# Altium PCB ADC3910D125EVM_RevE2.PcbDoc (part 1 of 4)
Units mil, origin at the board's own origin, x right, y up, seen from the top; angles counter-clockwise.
Board outline 4000 x 2716.54 mil, 6 copper layers (Top Layer, L2 GND, L3 PWR, L4 PWR, L5 GND, Bottom Layer), stack 60.99 mil thick; 318 components, 203 nets, 1298 pads, 559 vias.
Unrouted connection lines stored in the file: 5.
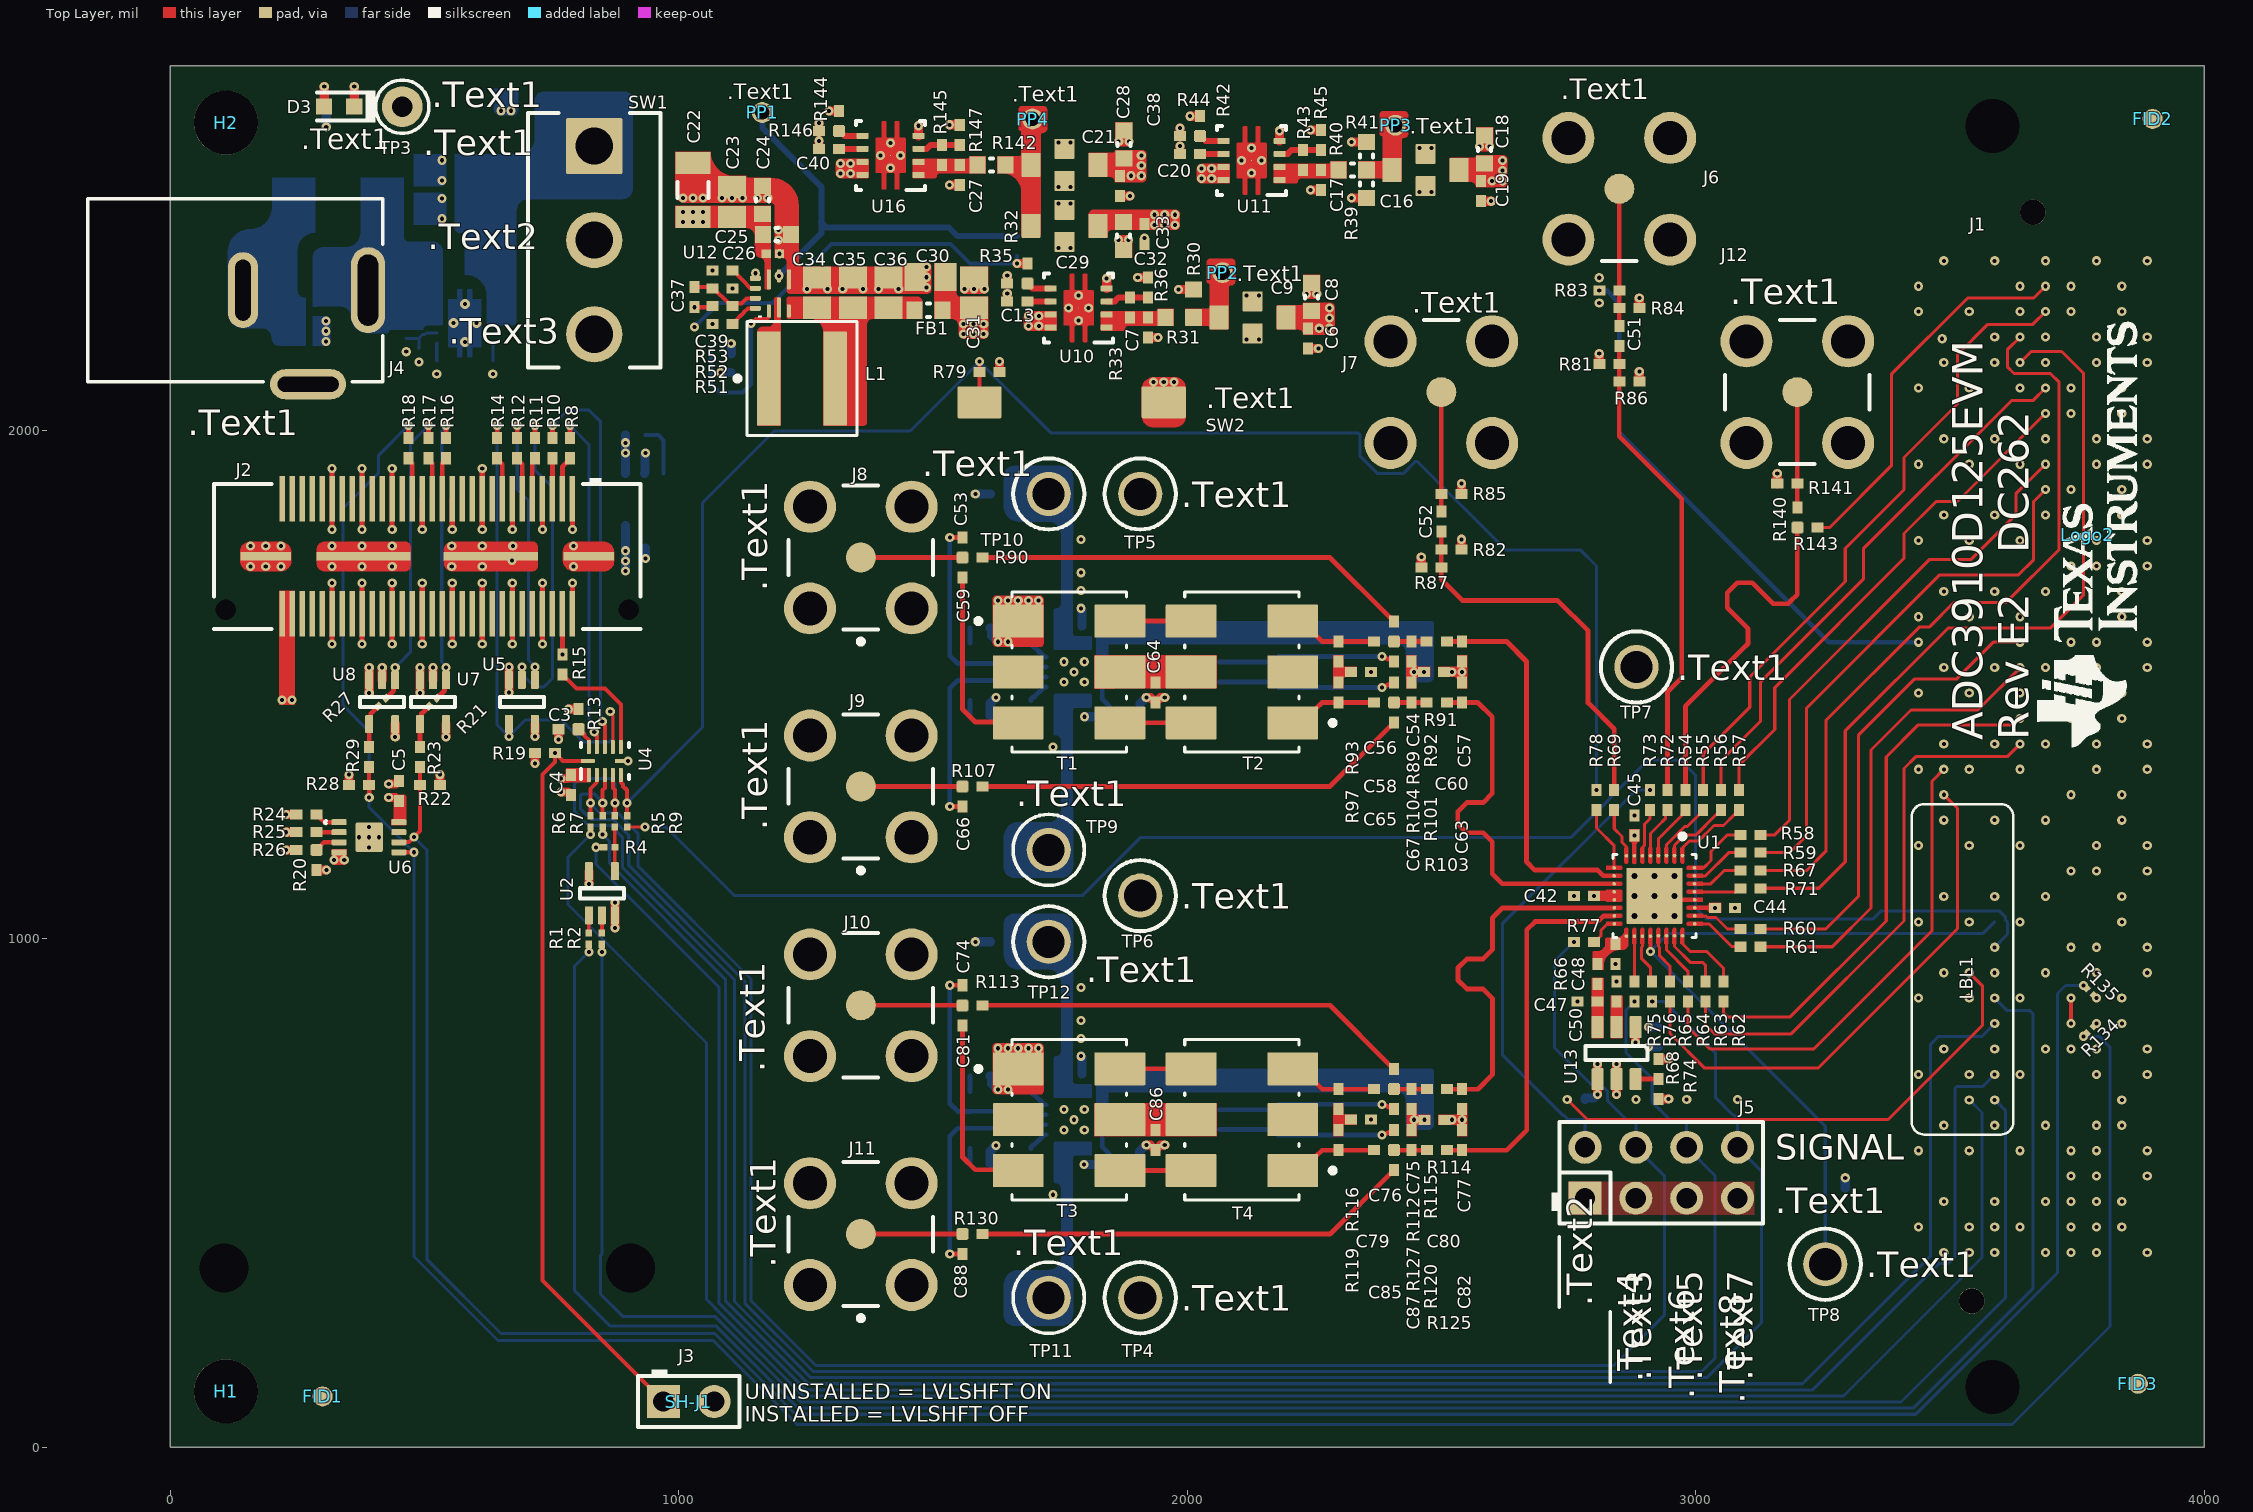
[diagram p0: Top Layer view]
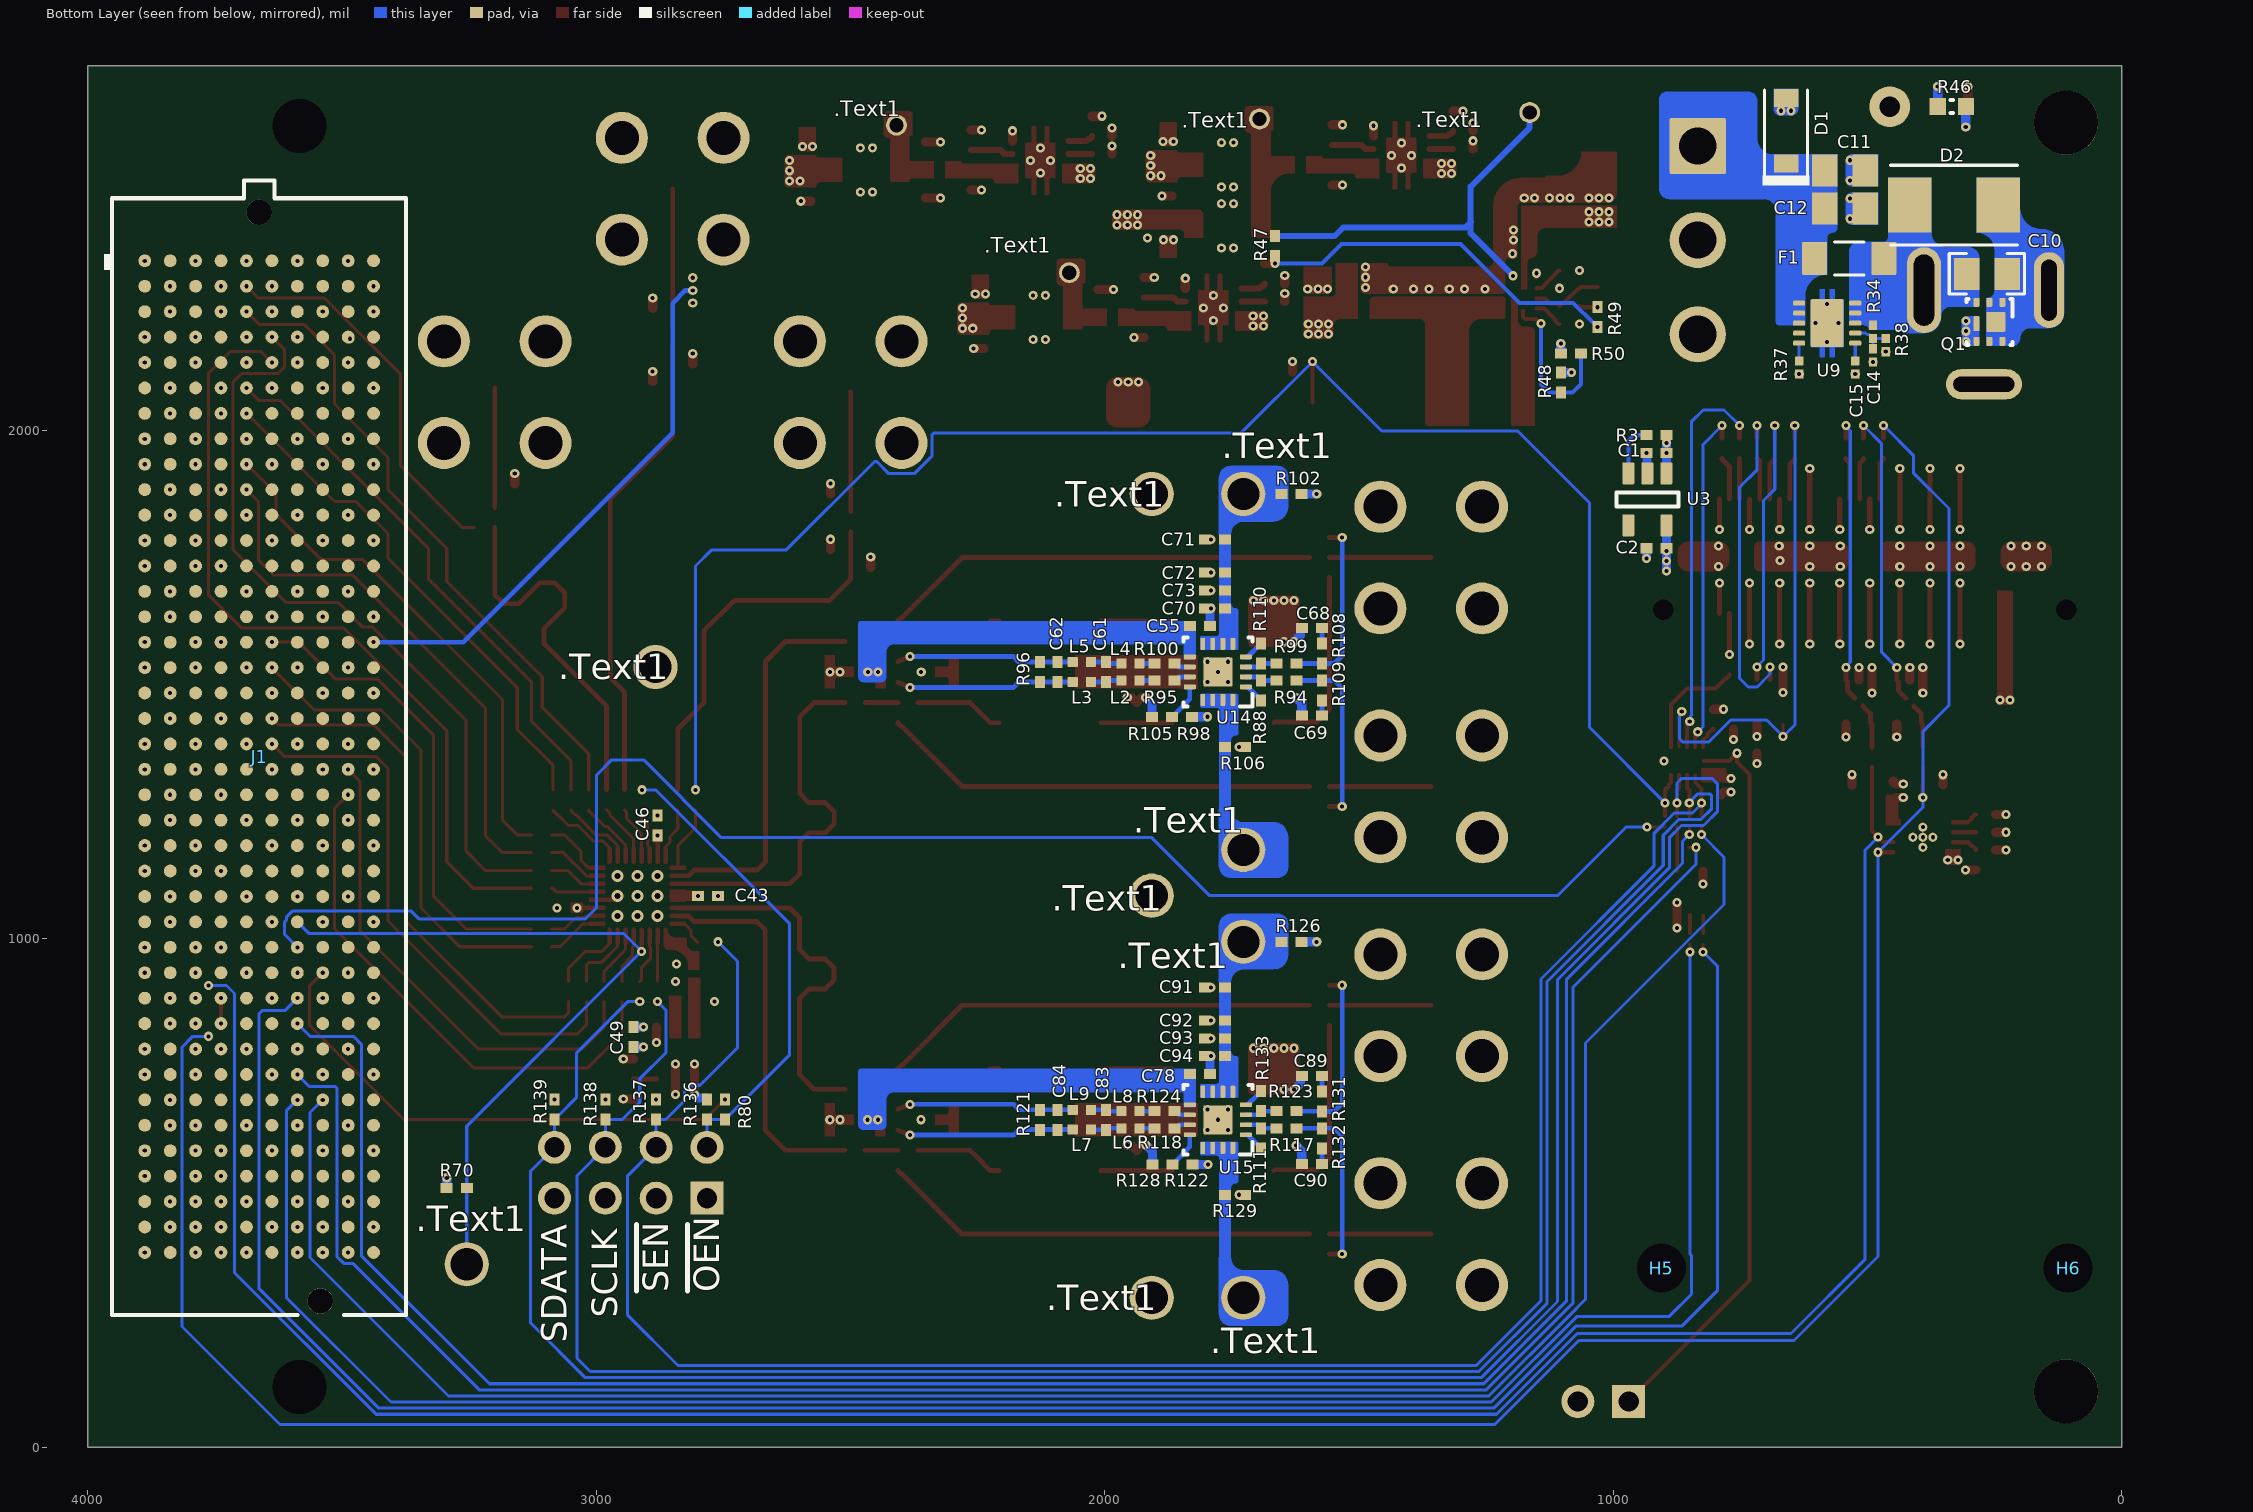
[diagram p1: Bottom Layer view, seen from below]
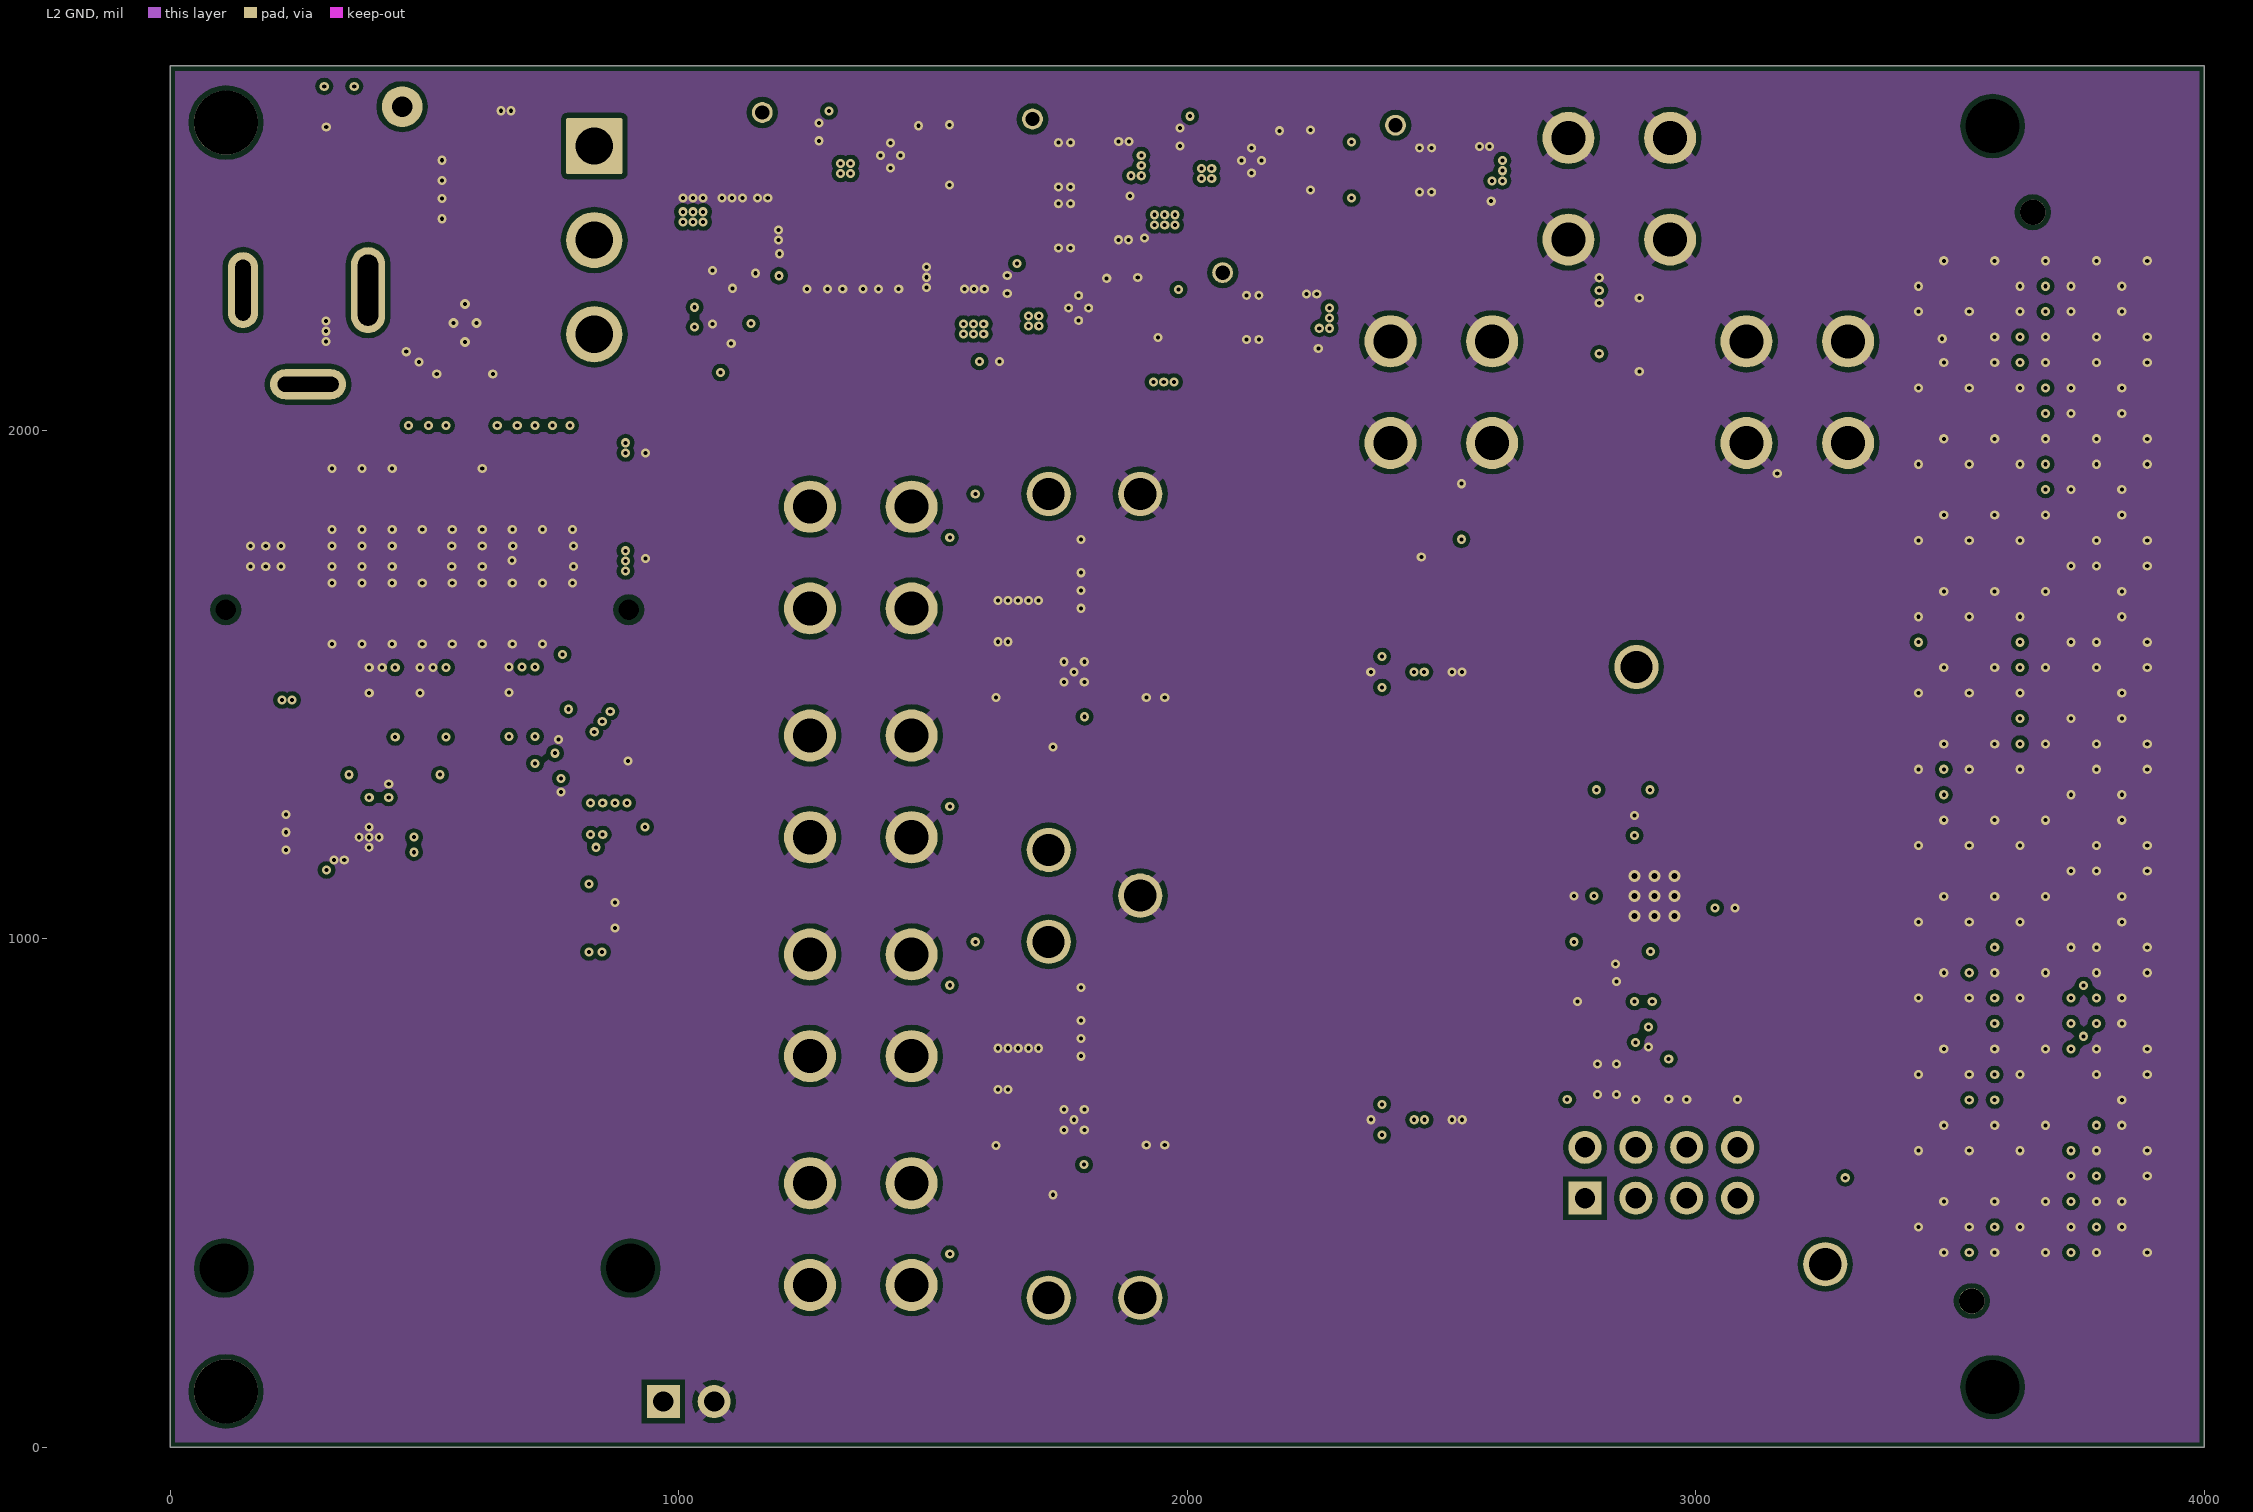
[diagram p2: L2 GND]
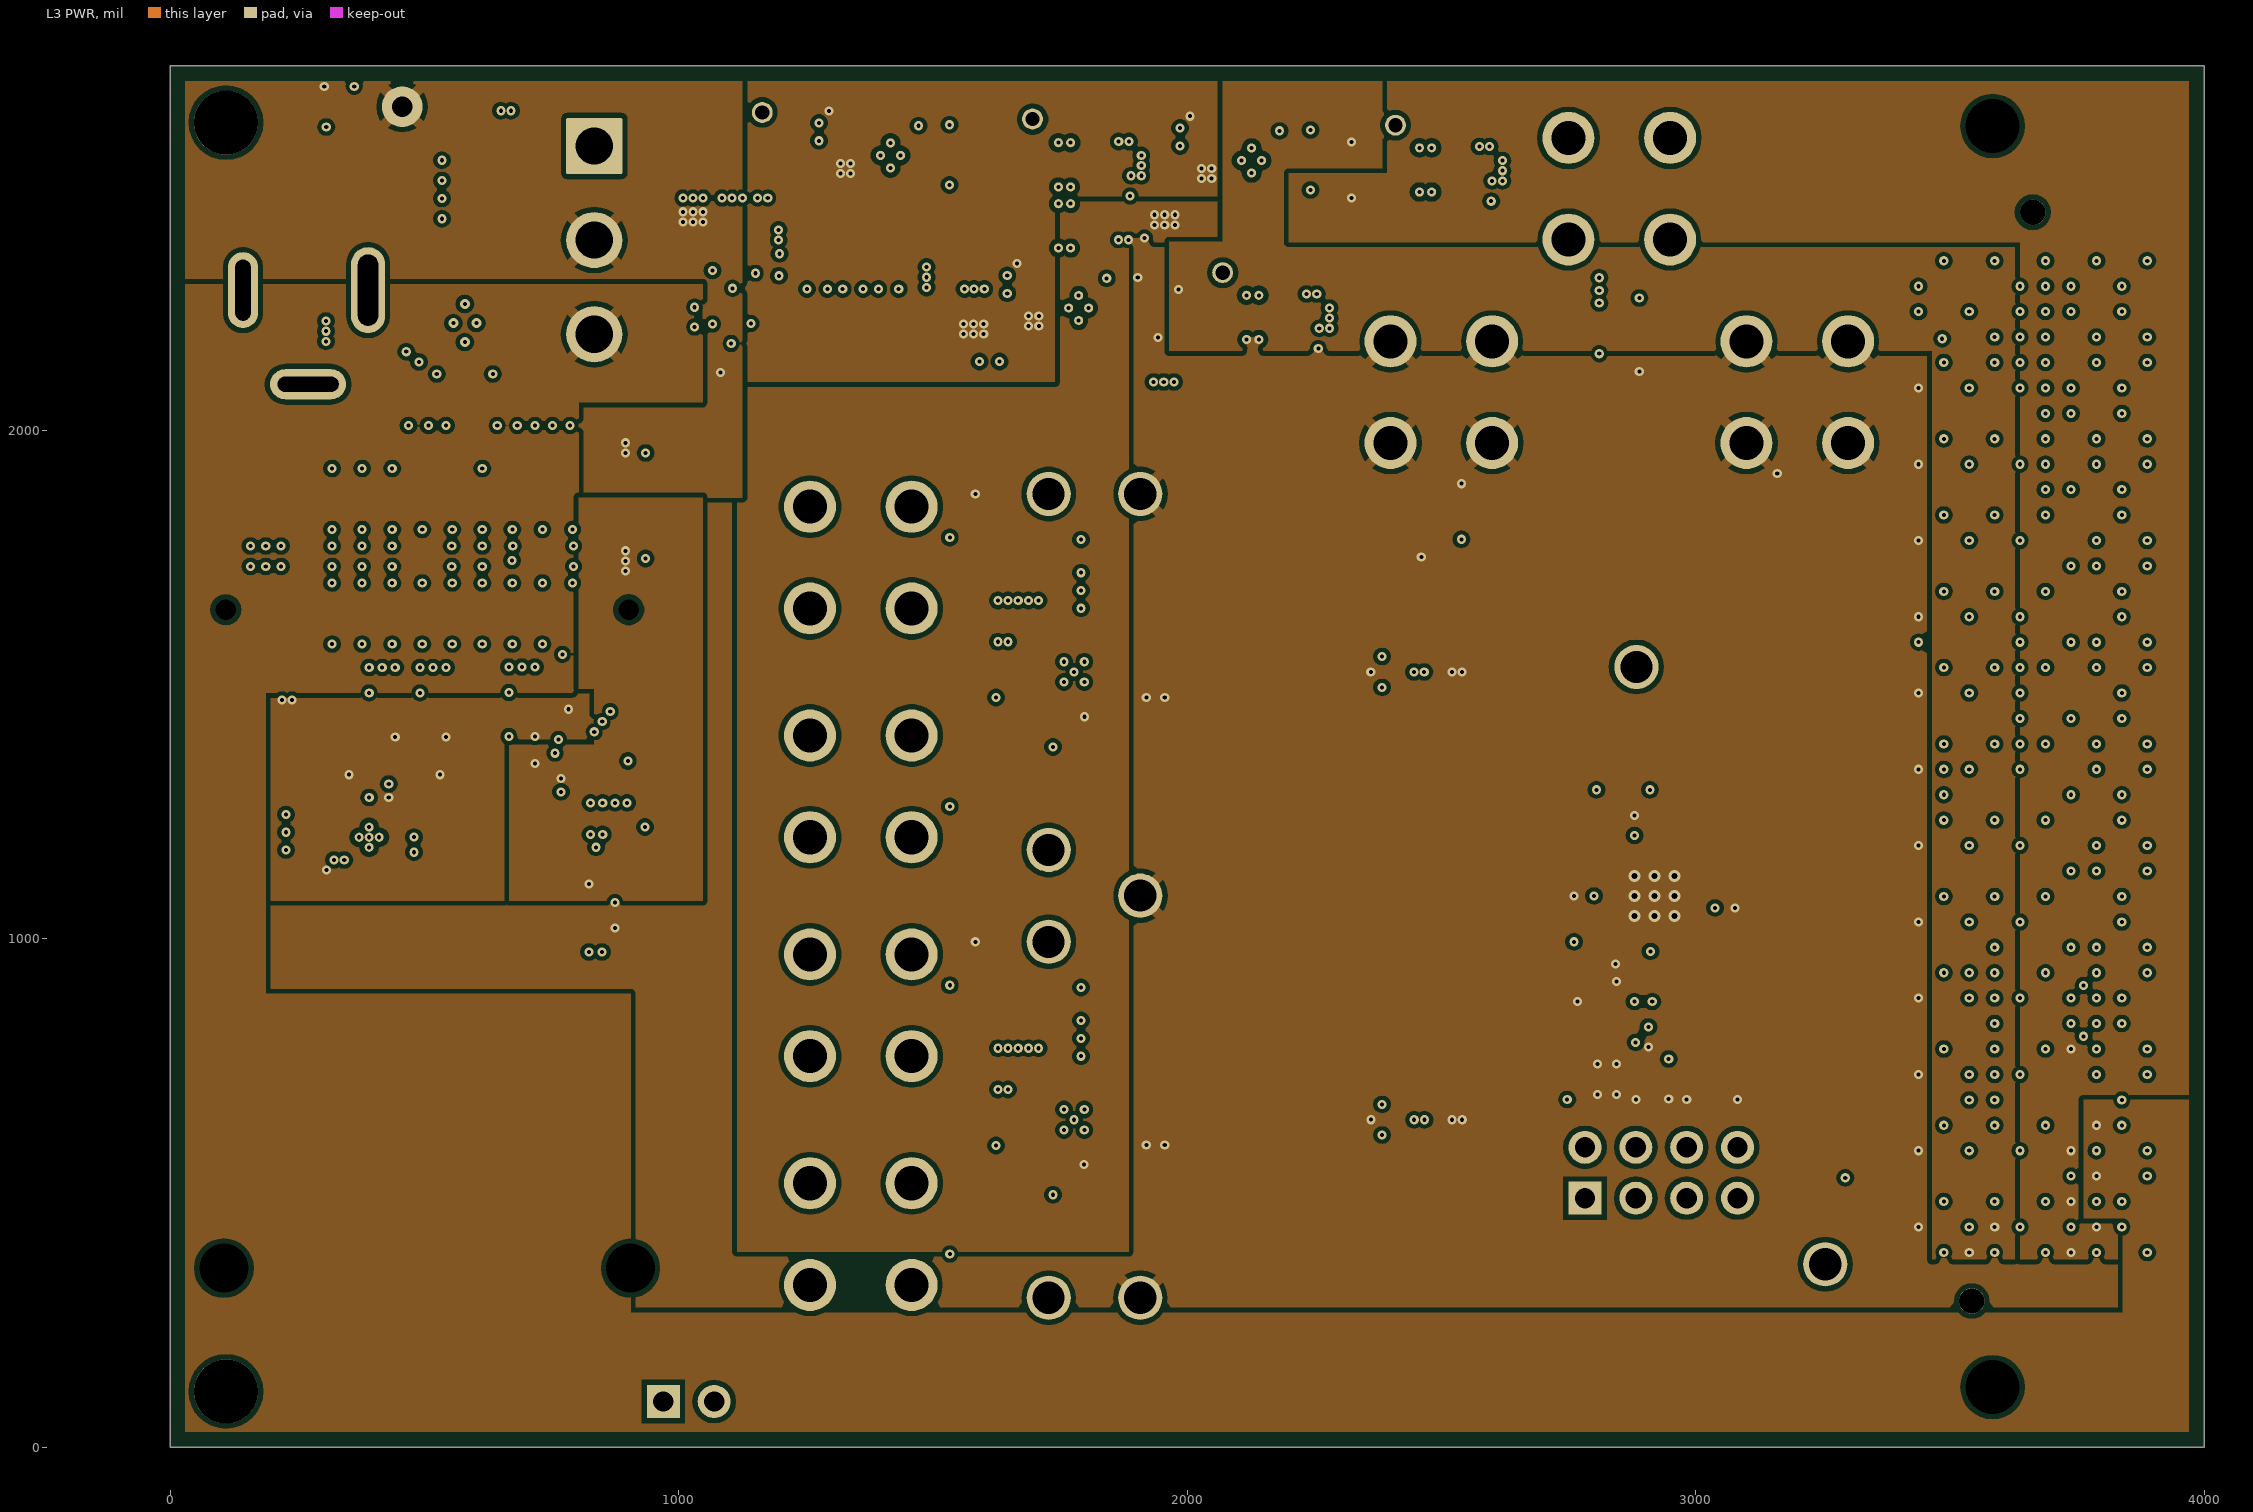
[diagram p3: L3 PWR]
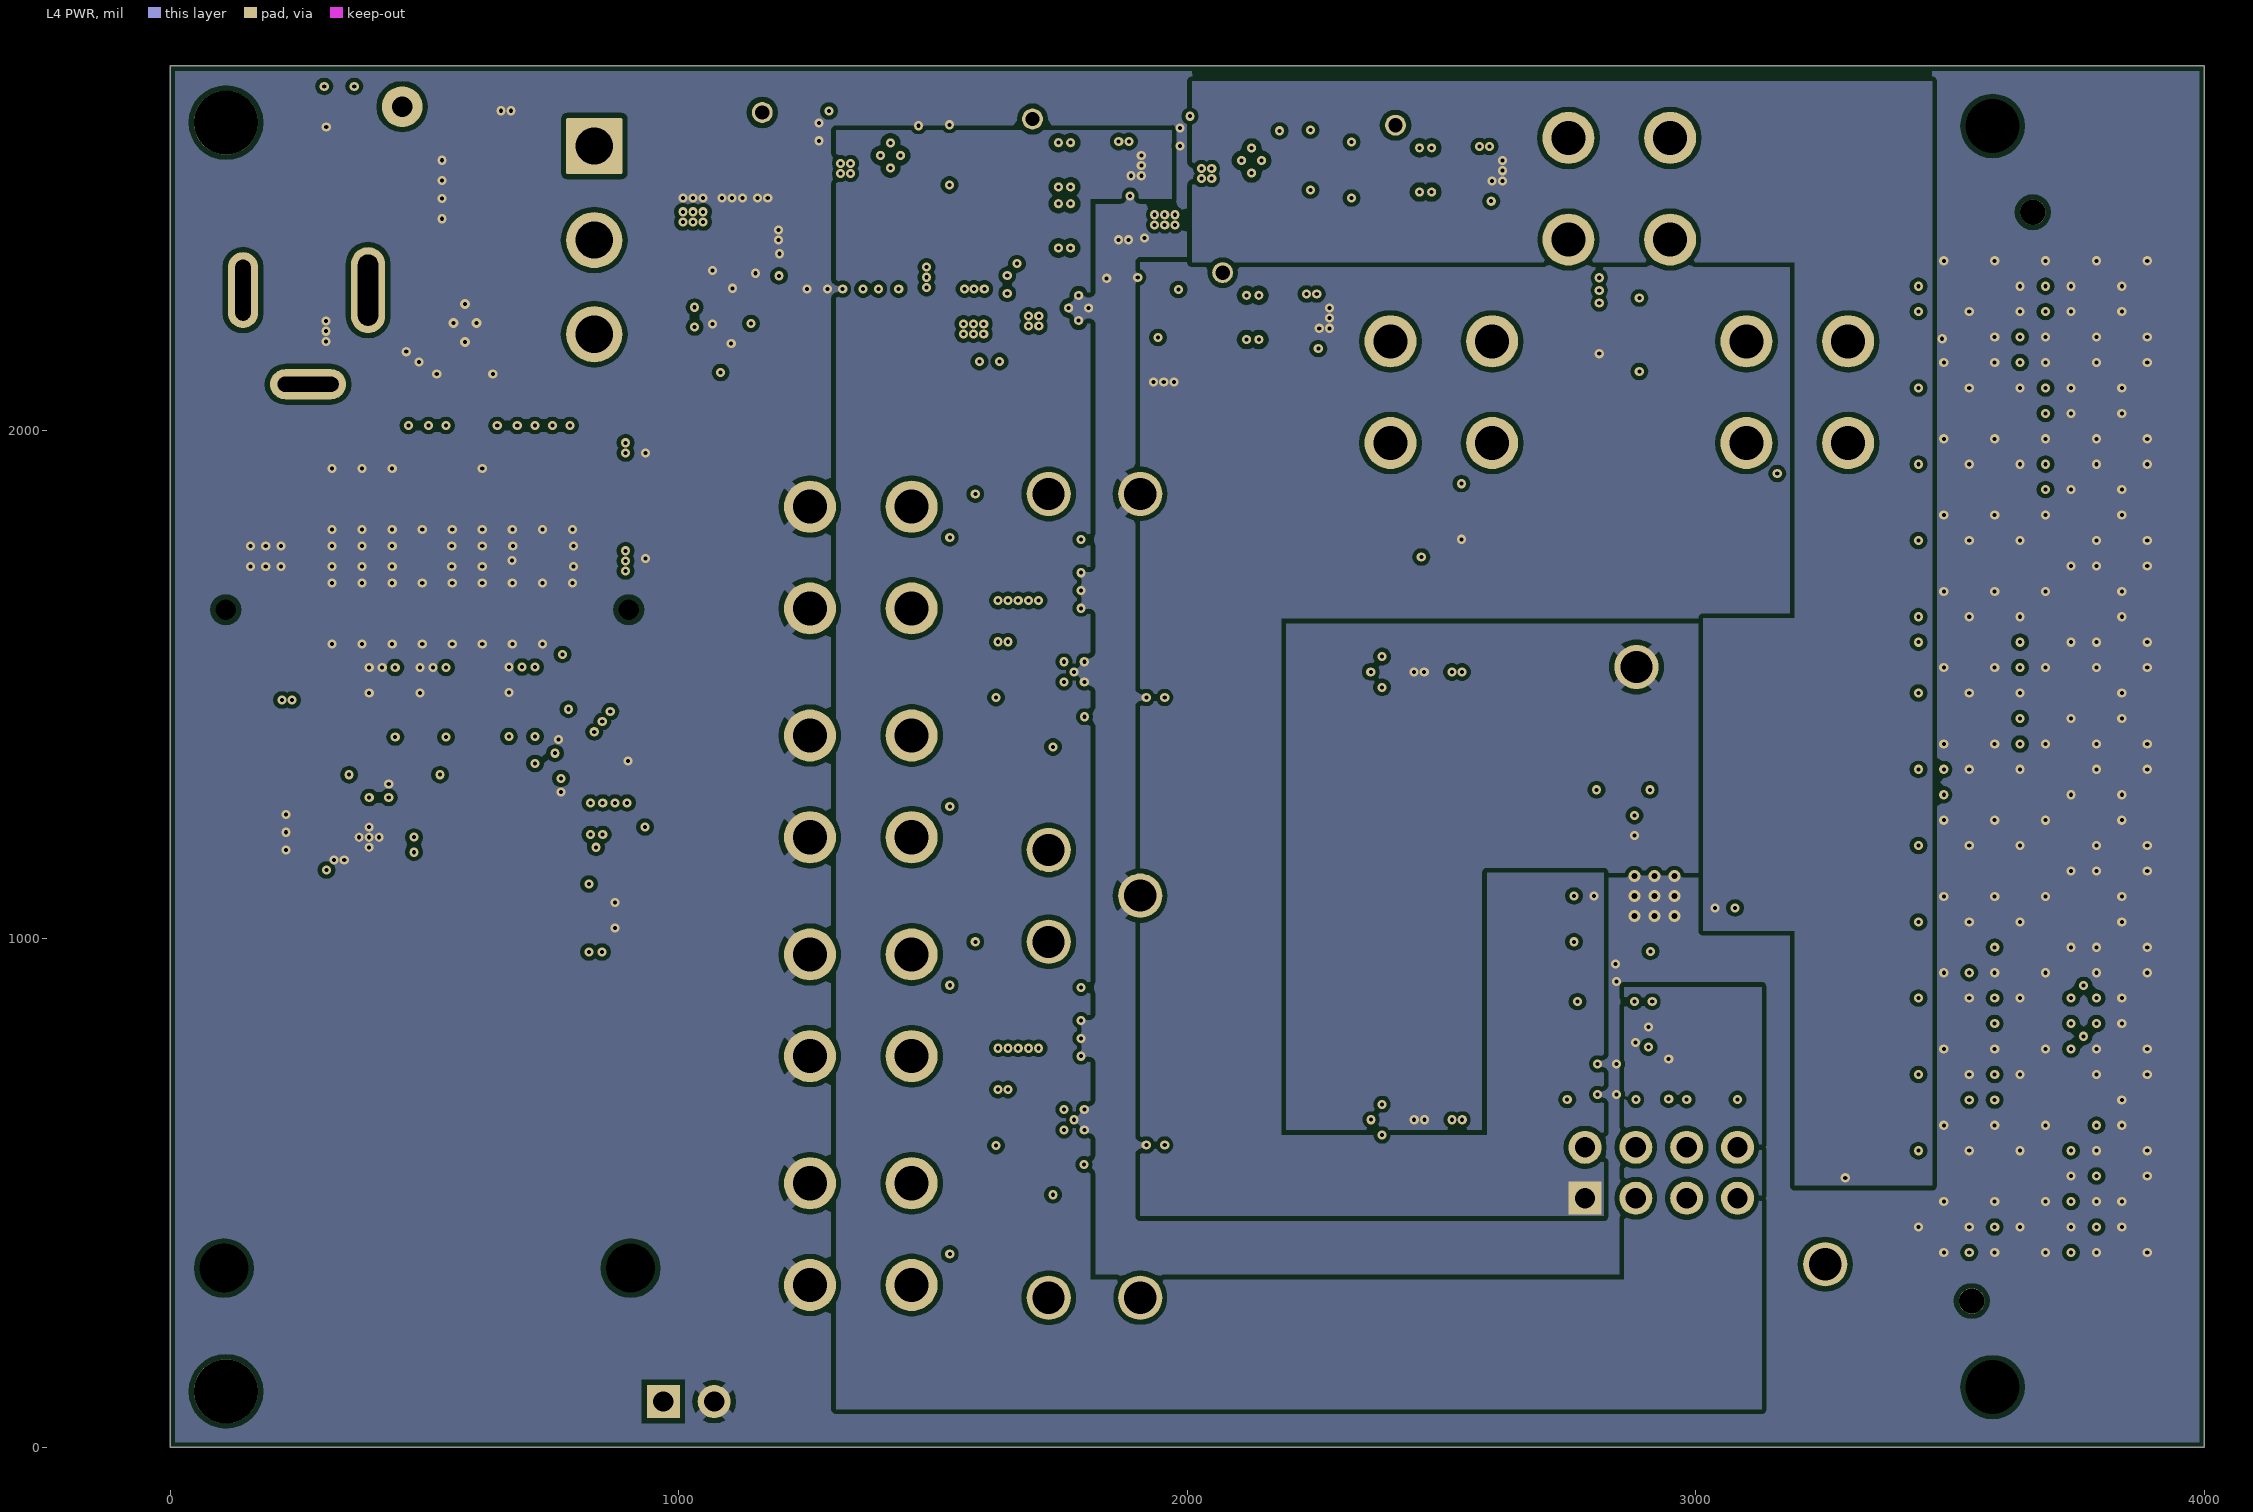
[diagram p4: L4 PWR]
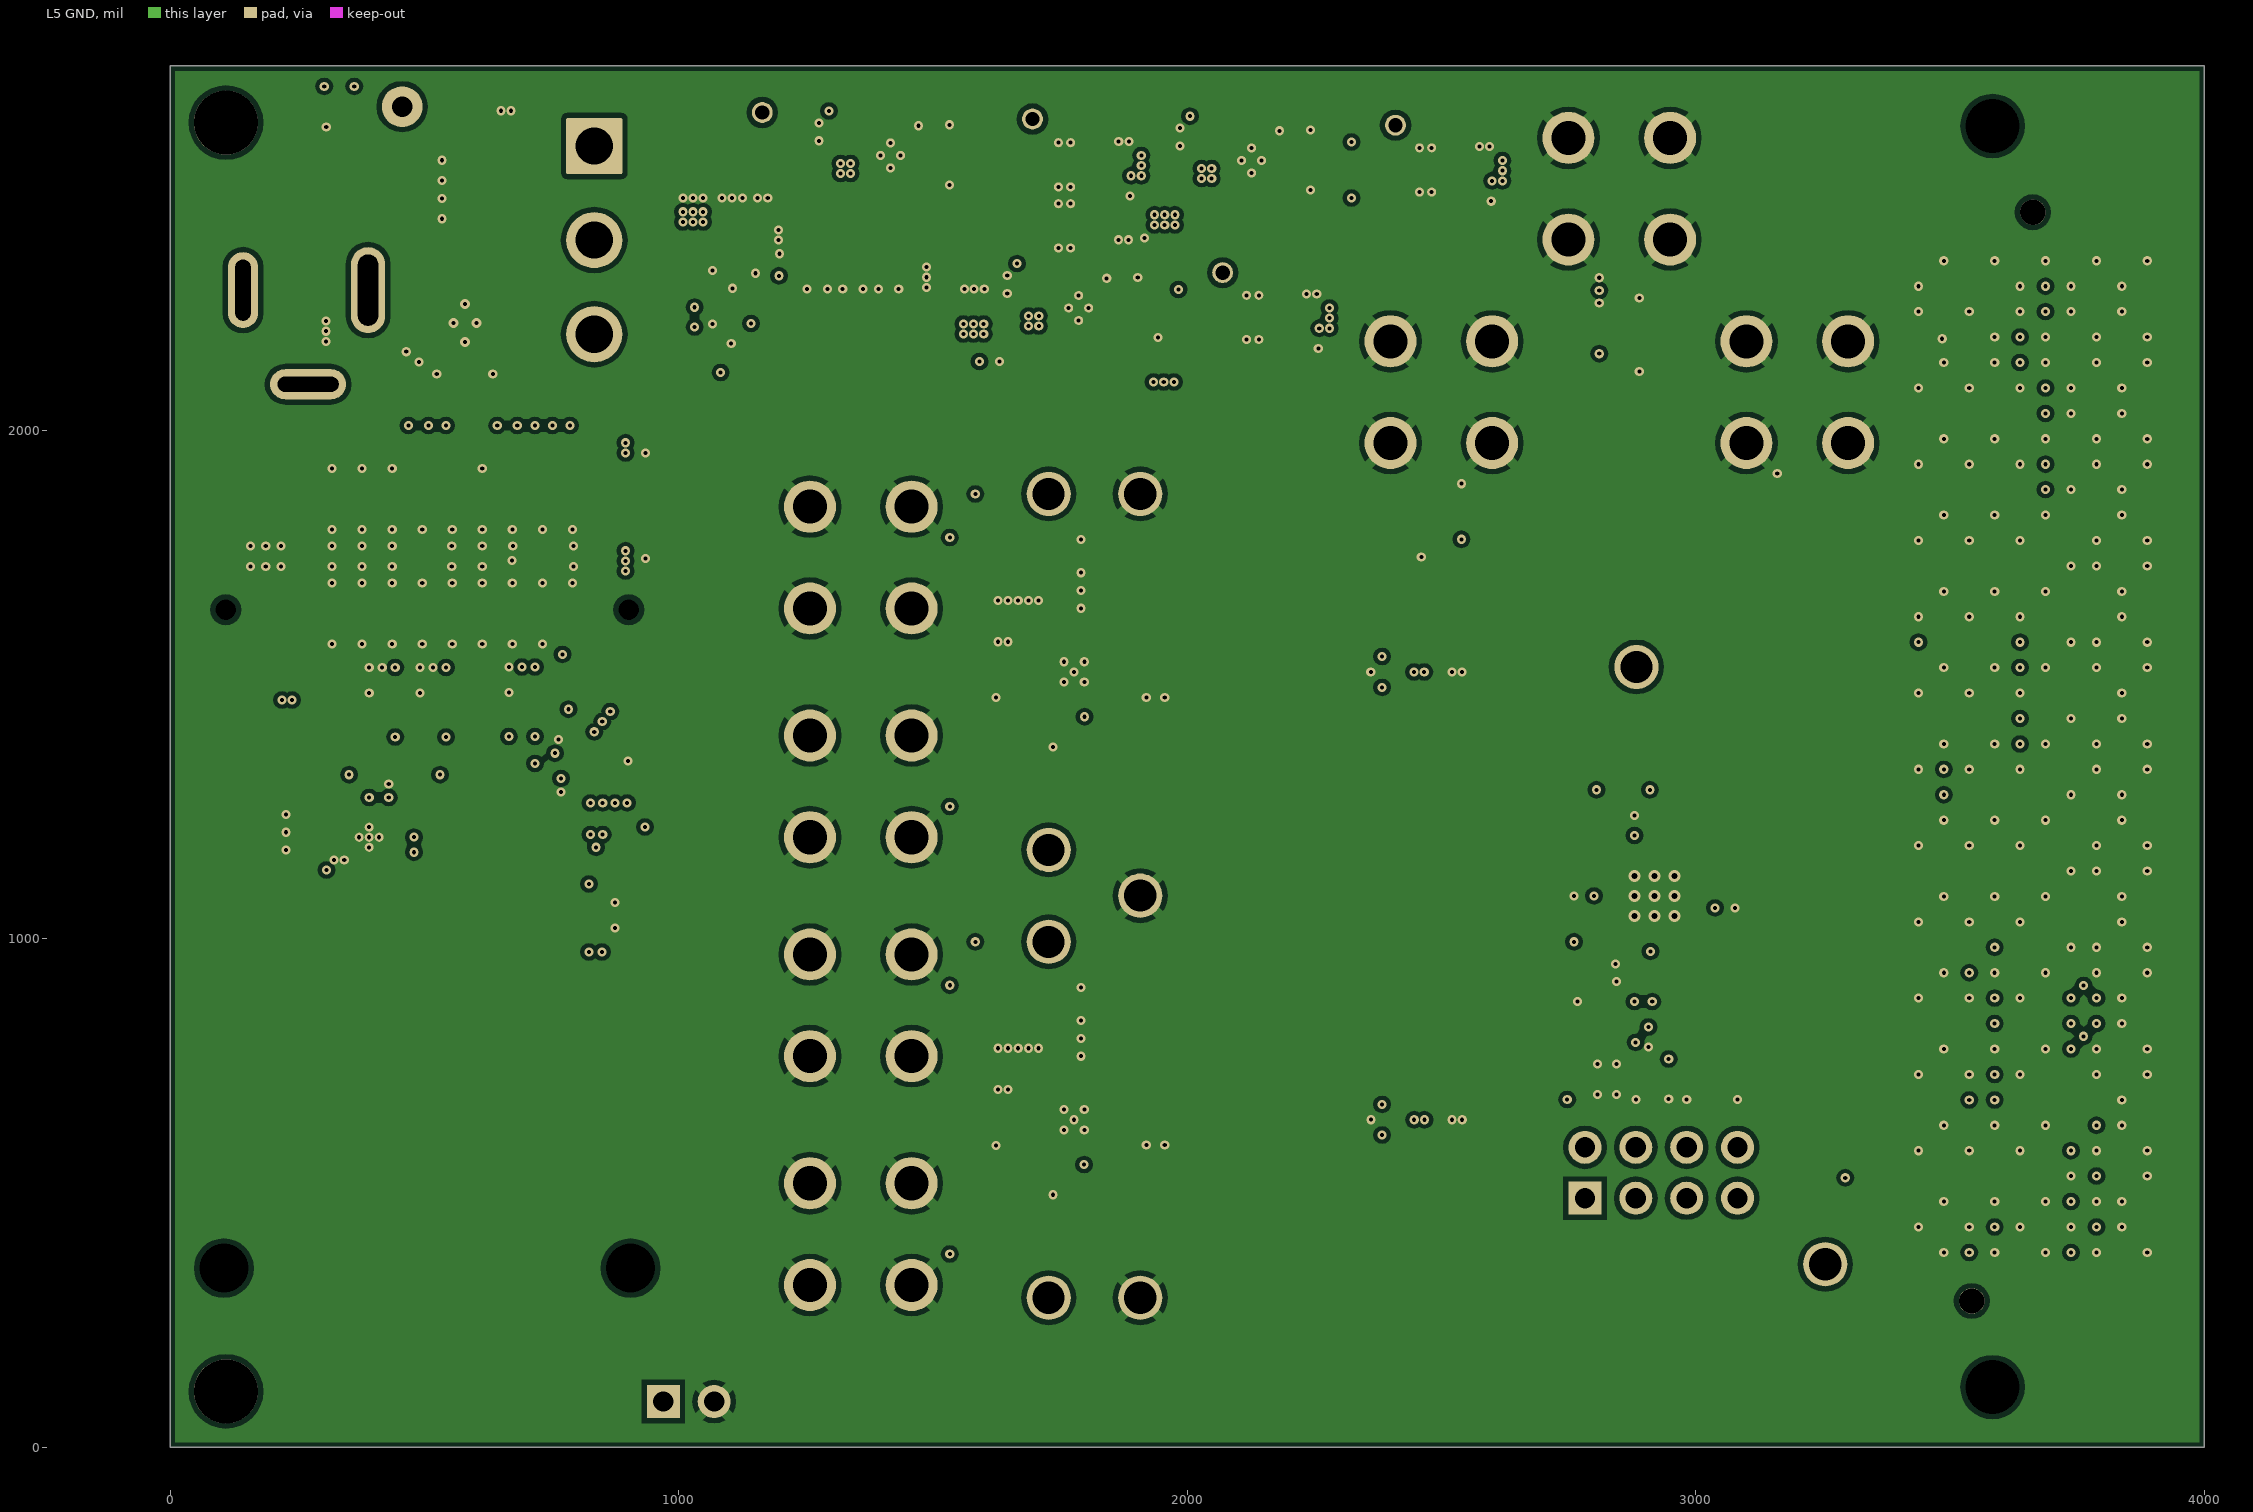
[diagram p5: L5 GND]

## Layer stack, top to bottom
Top Solder: solder mask 0.5, Solder Resist, Dk 3.5
Top Layer: signal copper 1.4
Dielectric1: core 5, FR4-370HR, Dk 3.88
L2 GND: signal copper 1.417
Dielectric 3: prepreg 2.8, PP-006, Dk 4.1
L3 PWR: signal copper 1.378
Dielectric 2: prepreg 37, FR4-370HR, Dk 4.05
L4 PWR: signal copper 1.378
Dielectric 4: prepreg 2.8, PP-006, Dk 4.1
L5 GND: signal copper 1.417
Dielectric 1: core 5, FR4-370HR, Dk 3.88
Bottom Layer: signal copper 1.4
Bottom Solder: solder mask 0.5, Solder Resist, Dk 3.5

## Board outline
0,0 4000,0 4000,2716.54 0,2716.54

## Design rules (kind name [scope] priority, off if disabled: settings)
AssemblyTestPointUsage [All] p1: valid=2
BoardOutlineClearance BoardOutlineClearance_MountingHoles [OnCopper and InComponentClass('Mounting Holes')] p1: gap=39.37 ignorepadtopadclearanceinfootprint=FALSE
BoardOutlineClearance BoardOutlineClearance_Poly_GND [OnCopper and IsPoly and Net = 'GND'] p2: gap=20 ignorepadtopadclearanceinfootprint=FALSE
BoardOutlineClearance BoardOutlineClearance_Poly [OnCopper and IsPoly and not(Net = 'GND')] p3: gap=30 ignorepadtopadclearanceinfootprint=FALSE
BoardOutlineClearance [OnCopper and Not InComponentClass('Logo') and not InComponentClass('FiducialMark') and not InRegion(1000,500,4000,800) and not InPoly] p4: gap=10 ignorepadtopadclearanceinfootprint=FALSE
Clearance Clearance_Keepouts [((IsTrack Or IsArc) And Not InPoly) And IsFree and IsKeepOut vs ((IsTrack Or IsArc) And Not InPoly) And IsFree and IsKeepOut] p1: gap=0 ignorepadtopadclearanceinfootprint=FALSE
Clearance Clearance_Poly [InPolygon] p2: gap=10 ignorepadtopadclearanceinfootprint=TRUE except(8: Via-Fill Via-Poly Via-Region Fill-Hole Poly-Hole Region-Hole)
Clearance Clearance_FiducialMark [IsKeepOut and InComponentClass('FiducialMark') vs IsPad and InComponentClass('FiducialMark')] p3: gap=0 ignorepadtopadclearanceinfootprint=FALSE
Clearance [All] p4: gap=6 ignorepadtopadclearanceinfootprint=TRUE except(8: Arc-Hole Track-Hole SMDPad-Hole THPad-Hole Via-Hole Fill-Hole Poly-Hole Region-Hole Text-Hole)
ComponentClearance ComponentClearance_MountingHoles_FiducialMarks [InComponentClass('Mounting Holes') vs InComponentClass('FiducialMark')] p1: gap=50 collisioncheckmode=3 verticalgap=10 showdistances=FALSE
ComponentClearance ComponentClearance_Shunt [InComponentClass('Header') vs InComponentClass('Shunt')] p2: gap=0 collisioncheckmode=3 verticalgap=0 showdistances=FALSE
ComponentClearance ComponentClearance_Logo [InComponentClass('Logo')] p3: gap=30 collisioncheckmode=3 verticalgap=10 showdistances=FALSE
ComponentClearance ComponentClearance_ScrewToNut [(HasFootprint('NY PMS 440 0025 PH')) vs (HasFootprint('Keystone_1902C'))] p4: gap=5 collisioncheckmode=3 verticalgap=10 showdistances=FALSE
ComponentClearance ComponentClearance_MountingHoles [InComponentClass('Mounting Holes')] p5: gap=100 collisioncheckmode=3 verticalgap=100000 showdistances=FALSE
ComponentClearance ComponentClearance_SmallPassives [HasFootprint('0201*') or HasFootprint('0402*') or HasFootprint('0508') or HasFootprint('0603*') or HasFootprint('0612') or HasFootprint('0805*') or HasFootprint('0815*') or HasFootprint('0830*') or HasFootprint('1206*') or HasFootprint('1210*') or HasFootprint('1808*') or HasFootprint('1812*') or HasFootprint('1825*') or HasFootprint('2010*') or HasFootprint('2220*') or HasFootprint('2225*') or HasFootprint('2512*') or HasFootprint('2728*') or HasFootprint('3518*') vs HasFootprint('0201*') or HasFootprint('0402*') or HasFootprint('0508') or HasFootprint('0603*') or HasFootprint('0612') or HasFootprint('0805*') or HasFootprint('0815*') or HasFootprint('0830*') or HasFootprint('1206*') or HasFootprint('1210*') or HasFootprint('1808*') or HasFootprint('1812*') or HasFootprint('1825*') or HasFootprint('2010*') or HasFootprint('2220*') or HasFootprint('2225*') or HasFootprint('2512*') or HasFootprint('2728*') or HasFootprint('3518*')] p6: gap=10 collisioncheckmode=3 verticalgap=10 showdistances=TRUE
ComponentClearance ComponentClearance_THtoSMT [IsThruComponent vs IsSMTComponent] p7: gap=30 collisioncheckmode=3 verticalgap=30 showdistances=FALSE donotcheckwithout3dbody=TRUE
ComponentClearance ComponentClearance_THtoTH [IsThruComponent vs IsThruComponent] p8: gap=20 collisioncheckmode=3 verticalgap=30 showdistances=FALSE donotcheckwithout3dbody=TRUE
ComponentClearance [All] p9: gap=10 collisioncheckmode=3 verticalgap=10 showdistances=FALSE
DiffPairsRouting [All] p1: maxlimit=100 minlimit=10 mostfreqgap=10 toplayer_minwidth=15 toplayer_maxwidth=15 toplayer_prefwidth=15 midlayer1_minwidth=15 midlayer1_maxwidth=15 midlayer1_prefwidth=15 midlayer2_minwidth=15 midlayer2_maxwidth=15 midlayer2_prefwidth=15 midlayer3_minwidth=15 midlayer3_maxwidth=15 midlayer3_prefwidth=15 midlayer4_minwidth=15 midlayer4_maxwidth=15 midlayer4_prefwidth=15 bottomlayer_minwidth=15 bottomlayer_maxwidth=15 bottomlayer_prefwidth=15 maxuncoupledlength=1000
FabricationTestPointUsage TestPointUsage [All] p1: valid=2 allowmultiple=FALSE
FabricationTestpoint Testpoint [All] p1: side=3 testpointundercomponent=TRUE minsize=40 maxsize=100 preferedsize=60 minholesize=0 maxholesize=40 preferedholesize=32 testpointgrid=1 allowsidetop=TRUE allowsidebottom=TRUE usegrid=TRUE gridtolerance=0.01
FanoutControl Fanout_LCC [IsLCC] p1: bgadir=Out bgaviamode=Centered fanoutstyle=Auto fanoutdirection=Alternating viagrid=1 // Fanout_LCC (Default Rule)
FanoutControl Fanout_BGA [IsBGA] p2: bgadir=Out bgaviamode=Centered fanoutstyle=Auto fanoutdirection=Alternating viagrid=1 // Fanout_BGA (Default Rule)
FanoutControl Fanout_Default [All] p4: bgadir=Out bgaviamode=Centered fanoutstyle=Auto fanoutdirection=Alternating viagrid=1 // Fanout_Default (Default Rule)
FanoutControl Fanout_Small [(CompPinCount < 5)] p5: bgadir=Out bgaviamode=Centered fanoutstyle=Auto fanoutdirection=OutThenIn viagrid=1 // Fanout_Small (Default Rule)
HoleSize [All] p1: absolutevalues=TRUE maxlimit=251 minlimit=7.87 maxpercent=80.000 minpercent=20.000
MatchedLengths MatchedLengths_clk [InNet('CLK') OR InNet('D00')] p1: tolerance=5 checknetsindiffpair=FALSE checkdiffpairvsdiffpair=TRUE checkxsignals=TRUE checkothers=TRUE
MatchedLengths "Analog Inputs" [InNetClass('Diff Input')] p2: tolerance=1 checknetsindiffpair=FALSE checkdiffpairvsdiffpair=TRUE checkxsignals=TRUE checkothers=TRUE
MinimumAnnularRing MinimumAnnularRing_ThermalPadVias [IsVia and InAnyComponent] p1: minimumring=5.91
MinimumAnnularRing [All] p2: minimumring=5
MinimumSolderMaskSliver MinimumSolderMaskSliver_Logo [InComponentClass('Logo') vs InComponentClass('Logo')] p1: minsoldermaskwidth=0.7
MinimumSolderMaskSliver [All] p2: minsoldermaskwidth=3.94
PlaneConnect [All] p1: planeconnectstyle=Relief reliefexpansion=10 reliefentries=4 reliefconductorwidth=10 reliefairgap=10
PolygonConnect PolygonConnect_2 [All vs IsNamedPolygon('TOP_LAYER_AVDD_P202')] p1: connectstyle=Direct reliefconductorwidth=10 reliefentries=4 polygonreliefangle="90 Angle" airgapwidth=10
PolygonConnect PolygonConnect_1 [All vs IsNamedPolygon('L4 PWR-AVDD')] p2: connectstyle=Direct reliefconductorwidth=10 reliefentries=4 polygonreliefangle="90 Angle" airgapwidth=10
PolygonConnect PolygonConnect_Via_Pads [IsPolygon vs IsPad and HoleSize <= 24] p3: connectstyle=Direct reliefconductorwidth=20 reliefentries=4 polygonreliefangle="45 Angle" airgapwidth=10
PolygonConnect [All] p4: thpad.connectstyle=Relief thpad.reliefconductorwidth=20 thpad.reliefentries=4 thpad.polygonreliefangle="45 Angle" thpad.airgapwidth=10 smdpad.connectstyle=Direct smdpad.reliefconductorwidth=10 smdpad.reliefentries=4 smdpad.polygonreliefangle="90 Angle" smdpad.airgapwidth=10 via.connectstyle=Direct via.reliefconductorwidth=10 via.reliefentries=4 via.polygonreliefangle="90 Angle" via.airgapwidth=10
RoutingVias ThermalPadVias [IsVia and InAnyComponent] p1: holewidth=7.87 width=19.68 viastyle="Through Hole" minholewidth=7.87 minwidth=19.68 maxholewidth=12.99 maxwidth=23.62
RoutingVias [All] p2: holewidth=16 width=34 viastyle="Through Hole" minholewidth=7.87 minwidth=6 maxholewidth=40 maxwidth=65
SilkToBoardRegionClearance [Not ((IsComment or IsDesignator) And (Hide <> 'False')) and not InRegion(1000,500,4000,800)] p1:
SilkToSilkClearance SilkToSilkClearance_Pb-FreeLogo [(HasFootprint('Pb-Free_Overlay_Medium') OR HasFootprint('Pb-Free_Overlay_Small')) vs (HasFootprint('Pb-Free_Overlay_Medium') OR HasFootprint('Pb-Free_Overlay_Small'))] p1: silktosilkclearance=0
SilkToSilkClearance [All] p2: silktosilkclearance=3.94
SilkToSolderMaskClearance SilkToComponentPadClearance [(IsPad or IsFill or IsRegion) and InAnycomponent] p1: minsilkscreentomaskgap=5 clearancetoexposedcopper=TRUE
SilkToSolderMaskClearance "Silk to Solder Mask Opening" [All] p2: minsilkscreentomaskgap=3.94 clearancetoexposedcopper=FALSE
SolderMaskExpansion [All] p1: expansion=1.97 istentingtop=FALSE
UnRoutedNet [All] p1: checkbadconnections=TRUE
Width [All] p1: maxlimit=40 minlimit=5 preferedwidth=10 toplayer_prefwidth=5 midlayer1_prefwidth=5 midlayer2_prefwidth=5 midlayer3_minwidth=6 midlayer4_minwidth=6 bottomlayer_prefwidth=5 minimp=50.000000 maximp=50.000000 favimp=50.000000 checkconnectedcopper=TRUE
14 further rules are at their usual default settings.

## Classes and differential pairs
net class "Diff Input": INAM INAP INBM INBP
net class Power: +12V +12V_JACK AVDD FDA_3V3 FMC_1.8V FMC_3.3V FMC_12V IOVDD REF_3p3V
component class ADC3910D125EVM_TSW1418_Header_RevE2: J1 R134 R135 R143
component class Shunt: SH-J1
net class SerialOutput: D00 D01 D02 D03 D04 D05 D06 D07 D08 D09 "D\C\L\K\ /FCLK" DCLK
component class ADC3910D125EVM_DUT_RevE2: C42 C43 C44 C45 C46 C47 C48 C49 C50 J5 R54 R55 R56 R57 R58 R59 R60 R61 R62 R63 R64 R65 R66 R67 R68 R69 R70 R71 R72 R73 R74 R75 R76 R77 R78 R79 R80 R136 R137 R138 R139 SW2 TP7 TP8 U1 U13
component class ADC3910D125EVM_Power_RevE2: C6 C7 C8 C9 C10 C11 C12 C13 C14 C15 C16 C17 C18 C19 C20 C21 C22 C23 C24 C25 C26 C27 C28 C29 C30 C31 C32 C33 C34 C35 C36 C37 C38 C39 C40 D1 D2 D3 F1 FB1 J4 L1 PP1 PP2 PP3 PP4 Q1 R30 R31 R32 R33 R34 R35 R36 R37 R38 R39 R40 R41 R42 R43 R44 R45 R46 R47 R48 R49 R50 R51 R52 R53 R142 R144 R145 R146 R147 SW1 TP3 TP4 TP5 TP6 U9 U10 U11 U12 U16 Y?
component class ADC3910D125EVM_AIN_CLK_RevE2: C51 C52 C53 C54 C55 C56 C57 C58 C59 C60 C61 C62 C63 C64 C65 C66 C67 C68 C69 C70 C71 C72 C73 C74 C75 C76 C77 C78 C79 C80 C81 C82 C83 C84 C85 C86 C87 C88 C89 C90 C91 C92 C93 C94 J6 J7 J8 J9 J10 J11 J12 L2 L3 L4 L5 L6 L7 L8 L9 R81 R82 R83 R84 R85 R86 R87 R88 R89 R90 R91 R92 R93 R94 R95 R96 R97 R98 R99 R100 R101 R102 R103 R104 R105 R106 R107 R108 R109 R110 R111 R112 R113 R114 R115 R116 R117 R118 R119 R120 R121 R122 R123 R124 R125 R126 R127 R128 R129 R130 R131 R132 R133 R140 R141 T1 T2 T3 T4 TP9 TP10 TP11 TP12 U14 U15
component class ADC3910D125EVM_USB_Control_RevE2: C1 C2 C3 C4 C5 J2 J3 R1 R2 R3 R4 R5 R6 R7 R8 R9 R10 R11 R12 R13 R14 R15 R16 R17 R18 R19 R20 R21 R22 R23 R24 R25 R26 R27 R28 R29 U2 U3 U4 U5 U6 U7 U8
component class ADC3910D125EVM_Hardware_RevE2: FID1 FID2 FID3 H1 H2 H5 H6 LBL1 Logo1 Logo2 SH-J1 ZZ1 ZZ2 ZZ3 ZZ4
component class AssemblyNote: ZZ1 ZZ2 ZZ3 ZZ4
component class Label: LBL1

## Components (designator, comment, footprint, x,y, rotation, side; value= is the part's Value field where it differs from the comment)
C1 "C1005X5R1A475K050BC" 0402L_cap 915.63,1955.37 r180 bottom value="4.7 uF"
C2 "CM05X5R225K10AH" 0402L_cap 915.63,1768.01 r180 bottom value="2.2 uF"
C3 "GRT155R71E104KE01J" 0402L_cap 783.82,1412.09 r0 top value="0.1 uF"
C4 "GRT155R71E104KE01J" 0402L_cap 788.5,1302.28 r90 top value="0.1 uF"
C5 "GRT155R71E104KE01J" 0402L_cap 449.83,1290.91 r270 top value="0.1 uF"
C6 "NFM31PC276B0J3L" NFM31PC 2129.06,2222.01 r0 top value=27uF
C7 "C1005X5R1A475K050BC" 0402L_cap 1922.99,2202.32 r90 top value="4.7 uF"
C8 "GRM188R61E106KA73J" 0603L_cap 2245,2262.44 r270 top value="10 uF"
C9 "GRT155R71E104KE01J" 0402L_cap 2238.11,2180.2 r90 top value="0.1 uF"
C10 "C0805C105K5RACTU" 0805_HV 265.62,2307.67 r180 bottom value=1uF
C11 "C0805C105K5RACTU" 0805_HV 544.56,2511 r180 bottom value=1uF
C12 "C0805C105K5RACTU" 0805_HV 544.56,2436 r180 bottom value=1uF
C13 "0402ZC103JAT2A" 0402L_cap 1666.07,2253.31 r0 top value="0.01 uF"
C14 "GRM033R71E102KA01D" 0201_033 489.52,2147.5 r270 bottom value=1000pF
C15 "GRM033R71E102KA01D" 0201_033 524.52,2123.5 r270 bottom value=1000pF
C16 "NFM31PC276B0J3L" NFM31PC 2469.06,2512.01 r0 top value=27uF
C17 "C1005X5R1A475K050BC" 0402L_cap 2262.99,2492.32 r90 top value="4.7 uF"
C18 "GRM188R61E106KA73J" 0603L_cap 2585,2552.44 r270 top value="10 uF"
C19 "GRT155R71E104KE01J" 0402L_cap 2578.11,2470.2 r90 top value="0.1 uF"
C20 "0402ZC103JAT2A" 0402L_cap 2006.07,2543.31 r0 top value="0.01 uF"
C21 "NFM31PC276B0J3L" NFM31PC 1759.05,2522.01 r0 top value=27uF
C22 "C3216X5R1E476M160AC" 1206_190L 1028.44,2472.8 r90 top value=47uF
C23 "GRM21BR61E226ME44L" 0805L 1105.44,2449.18 r90 top value=22uF
C24 "C1608X5R1E106M080AC" 0603L 1164.74,2453.12 r90 top value=10uF
C25 "C1608X5R1E106M080AC" 0603L 1193.28,2384.62 r0 top value=10uF
C26 "GRM033C81E104KE14D" 0201_033 1185.4,2347.18 r0 top value=0.1uF
C27 "C1005X5R1A475K050BC" 0402L_cap 1552.99,2502.32 r90 top value="4.7 uF"
C28 "GRM188R61E106KA73J" 0603L_cap 1875.59,2562.21 r270 top value="10 uF"
C29 "NFM31PC276B0J3L" NFM31PC 1759.05,2402.01 r0 top value=27uF
C30 "GRM21BR61E226ME44L" 0805L 1495.39,2301 r180 top value=22uF
C31 "GRM21BR61E226ME44L" 0805L 1581.32,2270.49 r90 top value=22uF
C32 "GRM188R61E106KA73J" 0603L_cap 1875.05,2382.18 r90 top value="10 uF"
C33 "GRT155R71E104KE01J" 0402L_cap 1916.05,2386.11 r90 top value="0.1 uF"
C34 "GRM21BR61E226ME44L" 0805L 1272.66,2270.49 r90 top value=22uF
C35 "GRM21BR61E226ME44L" 0805L 1342.78,2270.49 r90 top value=22uF
C36 "GRM21BR61E226ME44L" 0805L 1412.9,2270.49 r90 top value=22uF
C37 "GRM155R61E474KE01D" 0402L 1031.68,2261.69 r90 top value=0.47uF
C38 "GRT155R71E104KE01J" 0402L_cap 1868.11,2480.2 r90 top value="0.1 uF"
C39 "GRM155R61E474KE01D" 0402L 1086.36,2314.19 r180 top value=0.47uF
C40 "0402ZC103JAT2A" 0402L_cap 1296.07,2553.31 r0 top value="0.01 uF"
C42 "GRT155R71E104KE01J" 0402L_cap 2780.72,1084.49 r0 top value="0.1 uF"
C43 "GRT155R71E104KE01J" 0402L_cap 2780.72,1084.49 r0 bottom value="0.1 uF"
C44 "GRT155R71E104KE01J" 0402L_cap 3057.98,1060.87 r180 top value="0.1 uF"
C45 "0402ZD105KAT2A" 0402L_cap 2879.77,1222.92 r270 top value="1 uF"
C46 "GRT155R71E104KE01J" 0402L_cap 2879.77,1222.92 r270 bottom value="0.1 uF"
C47 "0402ZD105KAT2A" 0402L_cap 2787.69,876.38 r0 top value="1 uF"
C48 "GRT155R71E104KE01J" 0402L_cap 2842.37,970.44 r90 top value="0.1 uF"
C49 "GRT155R71E104KE01J" 0402L_cap 2927.18,806.7 r90 bottom value="0.1 uF"
C50 "GRT155R71E104KE01J" 0402L_cap 2844.77,896.07 r270 top value="0.1 uF"
C51 "GRT155R71E104KE01J" 0402L_cap 2850,2185.31 r90 top value="0.1 uF"
C52 "GRT155R71E104KE01J" 0402L_cap 2500,1820.31 r90 top value="0.1 uF"
C53 "0402YC104JAT4A" 0402L_cap 1558.43,1769.39 r90 top value="0.1 uF"
C54 "0402YC104JAT4A" 0402L_cap 2406.71,1604.39 r270 top value="0.1 uF"
C55 "GRT155R71E104KE01J" 0402L_cap 1813.4,1614.99 r0 bottom value="0.1 uF"
C56 "0402YC104JAT4A" 0402L_cap 2387.02,1584.7 r0 top value="0.1 uF"
C57 "0402YC104JAT4A" 0402L_cap 2540.7,1565.01 r90 top value="0.1 uF"
C58 "0402YC104JAT4A" 0402L_cap 2342.02,1524.7 r180 top value="0.1 uF"
C59 "0402YC104JAT4A" 0402L_cap 1558.43,1730.02 r270 top value="0.1 uF"
C60 "0402YC104JAT4A" 0402L_cap 2486.02,1524.82 r0 top value="0.1 uF"
C61 "04025C181KAT2A" 0402L_cap 1997.88,1524.88 r270 bottom value="180 pF"
C62 "04025C271JAT2A" 0402L_cap 2093.32,1524.88 r270 bottom value="270 pF"
C63 "0402YC104JAT4A" 0402L_cap 2540.7,1484.39 r90 top value="0.1 uF"
C64 "0402YC104JAT4A" 0402L_cap 1937.96,1484.33 r90 top value="0.1 uF"
C65 "0402YC104JAT4A" 0402L_cap 2387.02,1464.7 r0 top value="0.1 uF"
C66 "0402YC104JAT4A" 0402L_cap 1558.43,1280.01 r90 top value="0.1 uF"
C67 "0402YC104JAT4A" 0402L_cap 2406.71,1445.01 r90 top value="0.1 uF"
C68 "GRT155R71E104KE01J" 0402L_cap 1593.16,1611.06 r180 bottom value="0.1 uF"
C69 "GRT155R71E104KE01J" 0402L_cap 1593.16,1438.69 r180 bottom value="0.1 uF"
C70 "GRT155R71E104KE01J" 0402L_cap 1783.68,1649.99 r180 bottom value="0.1 uF"
C71 "GRT155R71E104KE01J" 0402L_cap 1783.68,1784.99 r180 bottom value="0.1 uF"
C72 "GRT155R71E104KE01J" 0402L_cap 1783.68,1719.99 r180 bottom value="0.1 uF"
C73 "GRT155R71E104KE01J" 0402L_cap 1783.68,1684.99 r180 bottom value="0.1 uF"
C74 "0402YC104JAT4A" 0402L_cap 1558.43,888.97 r90 top value="0.1 uF"
C75 "0402YC104JAT4A" 0402L_cap 2406.71,723.98 r270 top value="0.1 uF"
C76 "0402YC104JAT4A" 0402L_cap 2387.02,704.29 r0 top value="0.1 uF"
C77 "0402YC104JAT4A" 0402L_cap 2541.07,684.6 r90 top value="0.1 uF"
C78 "GRT155R71E104KE01J" 0402L_cap 1813.4,734.22 r0 bottom value="0.1 uF"
C79 "0402YC104JAT4A" 0402L_cap 2342.02,644.29 r180 top value="0.1 uF"
C80 "0402YC104JAT4A" 0402L_cap 2486.39,644.11 r0 top value="0.1 uF"
C81 "0402YC104JAT4A" 0402L_cap 1558.43,849.6 r270 top value="0.1 uF"
C82 "0402YC104JAT4A" 0402L_cap 2541.08,603.97 r90 top value="0.1 uF"
C83 "04025C181KAT2A" 0402L_cap 1997.88,644.11 r270 bottom value="180 pF"
C84 "04025C271JAT2A" 0402L_cap 2093.32,644.11 r270 bottom value="270 pF"
C85 "0402YC104JAT4A" 0402L_cap 2387.02,584.29 r0 top value="0.1 uF"
C86 "0402YC104JAT4A" 0402L_cap 1937.96,603.92 r90 top value="0.1 uF"
C87 "0402YC104JAT4A" 0402L_cap 2406.71,564.6 r90 top value="0.1 uF"
C88 "0402YC104JAT4A" 0402L_cap 1558.43,399.6 r90 top value="0.1 uF"
C89 "GRT155R71E104KE01J" 0402L_cap 1593.16,729.95 r180 bottom value="0.1 uF"
C90 "GRT155R71E104KE01J" 0402L_cap 1593.16,557.58 r180 bottom value="0.1 uF"
C91 "GRT155R71E104KE01J" 0402L_cap 1783.68,904.23 r180 bottom value="0.1 uF"
C92 "GRT155R71E104KE01J" 0402L_cap 1783.68,839.23 r180 bottom value="0.1 uF"
C93 "GRT155R71E104KE01J" 0402L_cap 1783.68,804.23 r180 bottom value="0.1 uF"
C94 "GRT155R71E104KE01J" 0402L_cap 1783.68,769.23 r180 bottom value="0.1 uF"
D1 "MBR130T1G" SOD-123 660.52,2588.96 r90 bottom value=30V
D2 "SMBJ15CA" SMB-Bi 330.12,2442.67 r0 bottom value=15V
D3 "LTST-C191TGKT" LED_LTST-C190-Green 332.74,2636.35 r0 top
F1 "SF-1206FP100-2" FP-SF-1206FP100-2_1206-MFG 536.33,2338.02 r0 bottom
FB1 "BLE18PS080SN1D" 0603L 1491.46,2236.04 r0 top value=-
FID1 "Fiducial Mark" Fiducial10-20 300,100 r0 top
FID2 "Fiducial Mark" Fiducial10-20 3898.9,2612.2 r0 top
FID3 "Fiducial Mark" Fiducial10-20 3870,125 r0 top
H1 "2069-440-SS" FP-2116-440-AL_STANDOFF_HEX_1-4-MFG 110,110 r0 top
H2 "2069-440-SS" FP-2116-440-AL_STANDOFF_HEX_1-4-MFG 110,2605 r0 top
H5 "HNSS256" HNSS256 905.79,352.2 r270 bottom
H6 "HNSS256" HNSS256 105.79,352.21 r270 bottom
J1 "ASP-134488-01" SAMTEC_ASP-134488-01 3663.19,1357.27 r90 top
J2 "QSH-030-01-L-D-A" FTDI_Dongle_003 505.79,1127.2 r90 top
J3 "PBC02SAAN" PBC02SAAN 1020,90 r90 top
J4 "RAPC722X" RAPC722X -169.31,2275.55 r0 top
J5 "PBC04DAAN" PBC04DAAN 2932.56,540 r90 top
J6 "132134-15" FP-132134-15_CONN_SMA_JACK-MFG 2850,2475 r0 top
J7 "132134-15" FP-132134-15_CONN_SMA_JACK-MFG 2500,2075 r0 top
J8 "132134-15" FP-132134-15_CONN_SMA_JACK-MFG 1358.43,1749.7 r90 top
J9 "132134-15" FP-132134-15_CONN_SMA_JACK-MFG 1358.43,1299.7 r90 top
J10 "132134-15" FP-132134-15_CONN_SMA_JACK-MFG 1358.43,869.29 r90 top
J11 "132134-15" FP-132134-15_CONN_SMA_JACK-MFG 1358.43,419.29 r90 top
J12 "132134-15" FP-132134-15_CONN_SMA_JACK-MFG 3200,2075 r0 top
L1 "XGL5030-222MEC" XGL5030 1242.9,2101.79 r0 top value="2.2 µH"
L2 "MLG1005S82NJT000" TDK_IND_0402 1950.17,1508.06 r0 bottom value="82 nH"
L3 "MLG1005SR33JT000" TDK_IND_0402 2045.6,1505.19 r0 bottom value="330 nH"
L4 "MLG1005S82NJT000" TDK_IND_0402 1950.17,1541.69 r0 bottom value="82 nH"
L5 "MLG1005SR33JT000" TDK_IND_0402 2045.6,1544.56 r0 bottom value="330 nH"
L6 "MLG1005S82NJT000" TDK_IND_0402 1950.17,627.3 r0 bottom value="82 nH"
L7 "MLG1005SR33JT000" TDK_IND_0402 2045.6,625.35 r0 bottom value="330 nH"
L8 "MLG1005S82NJT000" TDK_IND_0402 1950.17,660.93 r0 bottom value="82 nH"
L9 "MLG1005SR33JT000" TDK_IND_0402 2045.6,663.8 r0 bottom value="330 nH"
LBL1 "THT-14-423-10" Label_650x200 3525,940 r90 top
Logo1 "FCC disclaimer" FCC_disclaimer 4970,2725 r90 bottom
Logo2 "Texas Instruments" TI_Stacked_Overlay_Small 3770,1795 r90 top
PP1 "Probe Point" ProbePoint_TH_40mil 1164.74,2625 r90 top
PP2 "Probe Point" ProbePoint_TH_40mil 2070,2310 r0 top
PP3 "Probe Point" ProbePoint_TH_40mil 2410,2600 r0 top
PP4 "Probe Point" ProbePoint_TH_40mil 1696.14,2612.01 r0 top
Q1 "CSD15571Q2" DQK0006C 260.93,2213.28 r270 bottom value=20V
R1 "ERJ-1GN0R00C" 0201#1 823.69,1000.24 r90 top value="0 Ω"
R2 "ERJ-1GN0R00C" 0201#1 849.28,1000.24 r90 top value="0 Ω"
R3 "ERJ-2RKF1002X" 0402L 915.63,1990.37 r180 bottom value="10 kΩ"
R4 "ERJ-1GN0R00C" 0201#1 863.85,1179.92 r0 top value="0 Ω"
R5 "ERJ-1GN0R00C" 0201#1 874.87,1230.94 r270 top value="0 Ω"
R6 "ERJ-1GN0R00C" 0201#1 826.87,1230.94 r90 top value="0 Ω"
R7 "ERJ-1GN0R00C" 0201#1 850.87,1230.94 r90 top value="0 Ω"
R8 "ERJ-2GE0R00X" 0402L 786.54,1964.68 r90 top value="0 Ω"
R9 "ERJ-1GN0R00C" 0201#1 898.87,1230.94 r90 top value="0 Ω"
R10 "ERJ-2GE0R00X" 0402L 751.85,1964.68 r90 top value="0 Ω"
R11 "ERJ-2GE0R00X" 0402L 717.48,1964.68 r90 top value="0 Ω"
R12 "ERJ-2GE0R00X" 0402L 682.8,1964.68 r90 top value="0 Ω"
R13 "ERJ-2GE0R00X" 0402L 803.5,1431.77 r270 top value="0 Ω"
R14 "ERJ-2GE0R00X" 0402L 643.43,1964.68 r90 top value="0 Ω"
R15 "ERJ-2GE0R00X" 0402L 771.54,1539.72 r270 top value="0 Ω"
R16 "ERJ-2GE0R00X" 0402L 542.82,1964.68 r90 top value="0 Ω"
R17 "ERJ-2GE0R00X" 0402L 508.13,1964.68 r90 top value="0 Ω"
R18 "ERJ-2GE0R00X" 0402L 468.76,1964.68 r90 top value="0 Ω"
R19 "ERJ-2GEJ103X" 0402L 737.17,1365 r180 top value="10 kΩ"
R20 "ERJ-2GEJ103X" 0402L 287.58,1154.86 r270 top value="10 kΩ"
R21 "ERJ-1GN0R00C" 0201#1 517.23,1465.38 r225 top value="0 Ω"
R22 "ERJ-2GEJ222X" 0402L 511.32,1302.72 r0 top value="2.2 kΩ"
R23 "ERJ-2GE0R00X" 0402L 491.63,1357.4 r270 top value="0 Ω"
R24 "ERJ-2GEJ103X" 0402L 267.89,1244.54 r0 top value="10 kΩ"
R25 "ERJ-2GEJ103X" 0402L 267.89,1209.54 r0 top value="10 kΩ"
R26 "ERJ-2GEJ103X" 0402L 267.89,1174.54 r0 top value="10 kΩ"
R27 "ERJ-1GN0R00C" 0201#1 417.23,1465.38 r225 top value="0 Ω"
R28 "ERJ-2GEJ222X" 0402L 371.95,1302.72 r180 top value="2.2 kΩ"
R29 "ERJ-2GE0R00X" 0402L 391.63,1357.4 r270 top value="0 Ω"
R30 "ERJ-U030R00V" 0603L 2013.11,2249.57 r90 top value="0 Ω"
R31 "ERJ-U030R00V" 0603L 1985.55,2222.01 r180 top value="0 Ω"
R32 "ERJ-2RKF1002X" 0402L 1685.76,2307.99 r90 top value="10 kΩ"
R33 "ERJ-2RKF1272X" 0402L 1887.99,2241.69 r270 top value="12.7 kΩ"
R34 "RC0201JR-071ML" 0201#2 489.52,2193.49 r90 bottom value=1.0Meg
R35 "ERJ-2RKF1002X" 0402L 1666.07,2288.31 r0 top value="10 kΩ"
R36 "ERJ-2RKF1002X" 0402L 1922.99,2281.06 r270 top value="10 kΩ"
R37 "RC0201FR-7D45K3L" 0201#2 634.76,2123.5 r90 bottom value=45.3k
R38 "RC0201FS-7D4K99L" 0201#2 464.52,2167.5 r270 bottom value=4.99k
R39 "ERJ-U030R00V" 0603L 2353.11,2484.45 r270 top value="0 Ω"
R40 "ERJ-U030R00V" 0603L 2353.11,2539.57 r270 top value="0 Ω"
R41 "ERJ-U030R00V" 0603L 2325.55,2512.01 r180 top value="0 Ω"
R42 "ERJ-2RKF1002X" 0402L 2025.76,2597.99 r90 top value="10 kΩ"
R43 "ERJ-2RKF1272X" 0402L 2227.99,2531.69 r270 top value="12.7 kΩ"
R44 "ERJ-2RKF1002X" 0402L 2006.07,2578.31 r0 top value="10 kΩ"
R45 "ERJ-2RKF1002X" 0402L 2262.99,2571.06 r270 top value="10 kΩ"
R46 "ERJ-UP3F1502V" 0603L 334.71,2636.35 r0 bottom value="15 kΩ"
R47 "ERJ-2RKF1002X" 0402L 1665.76,2362.36 r270 bottom value="10 kΩ"
R48 "ERJ-2RKF1002X" 0402L 1102.82,2093.71 r90 bottom value="10 kΩ"
R49 "ERJ-2GE0R00X" 0402L 1031.68,2222.32 r270 bottom value=0
R50 "ERJ-2RKF1002X" 0402L 1083.87,2150.6 r180 bottom value="10 kΩ"
R51 "ERJ-2RKF18R2X" 0402L 1086.36,2209.19 r0 top value="18.2 Ω"
R52 "ERJ-2RKF1962X" 0402L 1086.36,2244.19 r180 top value="19.6 kΩ"
R53 "ERJ-2RKF4871X" 0402L 1086.36,2279.19 r180 top value="4.87 kΩ"
R54 "ERJ-2RKF1000X" 0402L 2980.06,1273.33 r90 top value="100 Ω"
R55 "ERJ-2RKF1000X" 0402L 3015.06,1273.33 r90 top value="100 Ω"
R56 "ERJ-2RKF1000X" 0402L 3050.06,1273.33 r90 top value="100 Ω"
R57 "ERJ-2RKF1000X" 0402L 3085.06,1273.33 r90 top value="100 Ω"
R58 "ERJ-2RKF1000X" 0402L 3107.57,1204.36 r0 top value="100 Ω"
R59 "ERJ-2RKF1000X" 0402L 3107.57,1169.36 r0 top value="100 Ω"
R60 "ERJ-2RKF1000X" 0402L 3107.57,1019.36 r0 top value="100 Ω"
R61 "ERJ-2RKF1000X" 0402L 3107.57,984.36 r0 top value="100 Ω"
R62 "ERJ-2RKF1000X" 0402L 3054.77,896.07 r270 top value="100 Ω"
R63 "ERJ-2RKF1000X" 0402L 3019.77,896.07 r270 top value="100 Ω"
R64 "ERJ-2RKF1000X" 0402L 2984.77,896.07 r270 top value="100 Ω"
R65 "ERJ-2RKF1000X" 0402L 2949.77,896.07 r270 top value="100 Ω"
R66 "ERJ-2GE0R00X" 0402L 2807.37,931.07 r90 top value="0 Ω"
R67 "ERJ-2RKF1000X" 0402L 3107.57,1134.36 r0 top value="100 Ω"
R68 "ERJ-2RKF1002X" 0402L 2927.18,743.7 r90 top value="10 kΩ"
R69 "ERJ-2GE0R00X" 0402L 2840.06,1273.33 r270 top value="0 Ω"
R70 "ERJ-2RKF1002X" 0402L 3274.68,510 r0 bottom value="10 kΩ"
R71 "ERJ-2RKF1000X" 0402L 3107.57,1099.36 r0 top value="100 Ω"
R72 "ERJ-2GE0R00X" 0402L 2945.06,1273.33 r270 top value="0 Ω"
R73 "ERJ-2GE0R00X" 0402L 2910.56,1273.33 r270 top value="0 Ω"
R74 "ERJ-2RKF1002X" 0402L 2927.18,704.33 r90 top value="10 kΩ"
R75 "ERJ-2GE0R00X" 0402L 2879.77,896.07 r90 top value="0 Ω"
R76 "ERJ-2GE0R00X" 0402L 2914.77,896.07 r90 top value="0 Ω"
R77 "ERJ-2GE0R00X" 0402L 2780.72,994.11 r0 top value="0 Ω"
R78 "ERJ-2GE0R00X" 0402L 2805.06,1273.33 r270 top value="0 Ω"
R79 "ERJ-2RKF1001X" 0402L 1611.64,2115 r180 top value="1 kΩ"
R80 "ERJ-2GE0R00X" 0402L 2747.56,664.68 r90 bottom value="0 Ω"
R81 "ERA-2ARB102X" 0402L 2830.32,2130.63 r180 top value="1 kΩ"
R82 "ERA-2ARB102X" 0402L 2519.68,1765.63 r0 top value="1 kΩ"
R83 "ERJ-2GE0R00X" 0402L 2830.32,2275 r180 top value="0 Ω"
R84 "ERJ-2RKF49R9X" 0402L 2869.69,2240 r180 top value="49.9 Ω"
R85 "ERJ-2RKF49R9X" 0402L 2519.69,1875 r180 top value="49.9 Ω"
R86 "ERA-2ARB102X" 0402L 2869.69,2095.63 r180 top value="1 kΩ"
R87 "ERA-2ARB102X" 0402L 2480.31,1730.63 r0 top value="1 kΩ"
R88 "ERJ-2RKF4990X" 0402L 1692.84,1488.38 r270 bottom value="499 Ω"
R89 "ERJ-2GE0R00X" 0402L 2406.71,1565.02 r270 top value="0 Ω"
R90 "ERJ-2GE0R00X" 0402L 1578.11,1749.7 r0 top value="0 Ω"
R91 "ERJ-2GE0R00X" 0402L 2491.02,1584.7 r0 top value="0 Ω"
R92 "ERA-2ARB102X" 0402L 2441.33,1565.01 r90 top value="1 kΩ"
R93 "ERJ-2RKF49R9X" 0402L 2297.34,1565.01 r90 top value="49.9 Ω"
R94 "ERJ-2RKF2000X" 0402L 1643.16,1508.06 r0 bottom value="200 Ω"
R95 "ERJ-2RKF37R4X" 0402L 1882.77,1508.06 r0 bottom value="37.4 Ω"
R96 "ERJ-2RKF4990X" 0402L 2127.32,1524.88 r270 bottom value="499 Ω"
R97 "ERJ-2RKF49R9X" 0402L 2297.34,1484.39 r90 top value="49.9 Ω"
R98 "ERJ-2GE0R00X" 0402L 1848.28,1436.63 r0 bottom value="0 Ω"
R99 "ERJ-2RKF2000X" 0402L 1643.16,1541.69 r0 bottom value="200 Ω"
R100 "ERJ-2RKF37R4X" 0402L 1882.77,1541.69 r0 bottom value="37.4 Ω"
R101 "ERA-2ARB102X" 0402L 2441.33,1484.39 r90 top value="1 kΩ"
R102 "ERJ-2GE0R00X" 0402L 1633.28,1874.88 r180 bottom value="0 Ω"
R103 "ERJ-2GE0R00X" 0402L 2491.02,1464.7 r0 top value="0 Ω"
R104 "ERJ-2GE0R00X" 0402L 2406.71,1484.39 r90 top value="0 Ω"
R105 "ERJ-2GEJ103X" 0402L 1887.65,1436.63 r180 bottom value="10 kΩ"
R106 "ERJ-2GE0R00X" 0402L 1744.31,1377.34 r0 bottom value="0 Ω"
R107 "ERJ-2GE0R00X" 0402L 1578.11,1299.7 r0 top value="0 Ω"
R108 "ERJ-2RKF27R0X" 0402L 1573.47,1561.37 r270 bottom value="27 Ω"
R109 "ERJ-2RKF27R0X" 0402L 1573.47,1488.38 r90 bottom value="27 Ω"
R110 "ERJ-2RKF4990X" 0402L 1692.84,1561.37 r90 bottom value="499 Ω"
R111 "ERJ-2RKF4990X" 0402L 1692.85,607.62 r90 bottom value="499 Ω"
R112 "ERJ-2GE0R00X" 0402L 2406.71,684.61 r270 top value="0 Ω"
R113 "ERJ-2GE0R00X" 0402L 1578.11,869.29 r0 top value="0 Ω"
R114 "ERJ-2GE0R00X" 0402L 2491.39,704.29 r0 top value="0 Ω"
R115 "ERA-2ARB102X" 0402L 2441.7,684.6 r90 top value="1 kΩ"
R116 "ERJ-2RKF49R9X" 0402L 2297.34,684.6 r90 top value="49.9 Ω"
R117 "ERJ-2RKF2000X" 0402L 1643.16,627.3 r0 bottom value="200 Ω"
R118 "ERJ-2RKF37R4X" 0402L 1882.76,627.3 r0 bottom value="37.4 Ω"
R119 "ERJ-2RKF49R9X" 0402L 2297.34,603.97 r90 top value="49.9 Ω"
R120 "ERA-2ARB102X" 0402L 2441.71,603.97 r90 top value="1 kΩ"
R121 "ERJ-2RKF4990X" 0402L 2127.32,644.11 r270 bottom value="499 Ω"
R122 "ERJ-2GE0R00X" 0402L 1847.29,555.87 r0 bottom value="0 Ω"
R123 "ERJ-2RKF2000X" 0402L 1643.16,660.92 r0 bottom value="200 Ω"
R124 "ERJ-2RKF37R4X" 0402L 1882.76,660.92 r0 bottom value="37.4 Ω"
R125 "ERJ-2GE0R00X" 0402L 2491.39,584.29 r0 top value="0 Ω"
R126 "ERJ-2GE0R00X" 0402L 1633.28,994.11 r180 bottom value="0 Ω"
R127 "ERJ-2GE0R00X" 0402L 2406.71,603.98 r270 top value="0 Ω"
R128 "ERJ-2GEJ103X" 0402L 1886.66,555.87 r180 bottom value="10 kΩ"
R129 "ERJ-2GE0R00X" 0402L 1744.31,496.58 r0 bottom value="0 Ω"
R130 "ERJ-2GE0R00X" 0402L 1578.11,419.29 r0 top value="0 Ω"
R131 "ERJ-2RKF27R0X" 0402L 1573.47,680.26 r270 bottom value="27 Ω"
R132 "ERJ-2RKF27R0X" 0402L 1573.48,607.62 r90 bottom value="27 Ω"
R133 "ERJ-2RKF4990X" 0402L 1692.85,680.61 r270 bottom value="499 Ω"
R134 "CRCW02010000Z0ED" 0201L 3775.69,895.76 r315 top value=0
R135 "CRCW02010000Z0ED" 0201L 3775.69,820.78 r45 top value=0
R136 "ERJ-2RKF1002X" 0402L 2782.56,664.69 r270 bottom value="10 kΩ"
R137 "ERJ-2RKF1002X" 0402L 2882.56,664.15 r270 bottom value="10 kΩ"
R138 "ERJ-2RKF1002X" 0402L 2982.56,664.15 r270 bottom value="10 kΩ"
R139 "ERJ-2RKF1002X" 0402L 3082.56,664.15 r270 bottom value="10 kΩ"
R140 "ERJ-2GE0R00X" 0402L 3200,1828.58 r270 top value="0 Ω"
R141 "ERJ-2RKF49R9X" 0402L 3180.31,1895 r0 top value="49.9 Ω"
R142 "ERJ-U030R00V" 0603L 1615.55,2522.01 r180 top value="0 Ω"
R143 "ERJ-2GE0R00X" 0402L 3219.68,1808.9 r0 top value="0 Ω"
R144 "ERJ-2RKF1002X" 0402L 1315.76,2607.99 r90 top value="10 kΩ"
R145 "ERJ-2RKF3092X" 0402L 1517.99,2541.69 r270 top value="30.9 kΩ"
R146 "ERJ-2RKF1002X" 0402L 1296.07,2588.31 r0 top value="10 kΩ"
R147 "ERJ-2RKF1002X" 0402L 1552.99,2581.06 r270 top value="10 kΩ"
SH-J1 "SPC02SYAN" SPC02SYAN 1020,90 r180 top value=1x2
SW1 "1101M2S3CGE2" FP-1101M2S3CGE2_SIP3-MFG 834.25,2373.91 r0 top
SW2 "FSMSM" FSMSM 1773.05,2055 r180 top
T1 "ADT2-1T+" FP-ADT2-1T+_SMD6-MFG 1767.96,1524.7 r0 top
T2 "ADT2-1T+" FP-ADT2-1T+_SMD6-MFG 2107.96,1524.7 r180 top
T3 "ADT2-1T+" FP-ADT2-1T+_SMD6-MFG 1767.96,644.29 r0 top
T4 "ADT2-1T+" FP-ADT2-1T+_SMD6-MFG 2107.96,644.29 r180 top
TP3 "5000" Keystone5000 456.57,2636.35 r0 top
TP4 "5011" Keystone5011 1907.96,294.11 r0 top
TP5 "5011" Keystone5011 1907.96,1874.88 r0 top
TP6 "5011" Keystone5011 1907.96,1084.88 r0 top
TP7 "5013" Keystone5013 2883.71,1534.54 r0 top
TP8 "5013" Keystone5013 3255,360 r0 top
TP9 "5129" Keystone5129 1727.96,1174.88 r90 top
TP10 "5010" Keystone5010 1727.96,1874.88 r90 top
TP11 "5129" Keystone5129 1727.96,294.11 r90 top
TP12 "5010" Keystone5010 1727.96,994.11 r90 top
U1 "PADC392S125RSNR" RSN0032B-MFG 2919.14,1084.49 r270 top
U2 "SN74LVC1G125DCK" DCK0005A 849.28,1089.57 r90 top
U3 "TPS70918DBVR" DBV0005A 933.35,1864.19 r270 bottom
U4 "LSF0204RUT" RUT0012A 855,1349.53 r90 top
U5 "SN74LVC1G125DCK" DCK0005A 691.89,1466.06 r270 top
U6 "24LC64FT-I/MNY" TDFN8 391.63,1199.7 r0 top
U7 "SN74LVC1G125DCK" DCK0005A 517.22,1465.39 r270 top
U8 "SN74LVC1G125DCK" DCK0005A 417.22,1465.39 r270 top
U9 "TPS259261DRCR" DRC0010J 579.64,2210.86 r0 bottom
U10 "TPS7A8001DRB" DRB0008A 1786.87,2240.51 r180 top
U11 "TPS7A8001DRB" DRB0008A 2126.87,2530.51 r180 top
U12 "TPS62913RPUT" RPU0010A 1187.46,2269.35 r90 top
U13 "REF35160QDBVR" DBV0006A 2844.77,775.2 r90 top
U14 "THS4541IRGTR" RGT0016A_NV 1777.96,1524.88 r0 bottom
U15 "THS4541IRGTR" RGT0016A_NV 1777.96,644.11 r0 bottom
U16 "TPS7A8001DRB" DRB0008A 1416.87,2540.51 r180 top
ZZ1 "This Assembly Note is for PCB labels only" AssemblyNoteLabel 65,7800 r0 top
ZZ2 "These assemblies are ESD sensitive, ESD precautions shall be observed." AssemblyNote 65,7700 r0 top
ZZ3 "These assemblies must be clean and free from flux and all contaminants. Use of no clean flux is not acceptable." AssemblyNote 65,7600 r0 top
ZZ4 "These assemblies must comply with workmanship standards IPC-A-610 Class 2, unless otherwise specified." AssemblyNote 65,7500 r0 top

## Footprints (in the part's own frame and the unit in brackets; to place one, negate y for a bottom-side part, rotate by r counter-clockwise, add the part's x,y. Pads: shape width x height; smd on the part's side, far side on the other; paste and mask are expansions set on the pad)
0201#1 [mm] "Data from Kemet datasheet CC101_COM dated 7/28/11"
  rect 0.36x0.32 smd mask+0.048: 1(-0.28,0) 2(0.28,0)
  body extent -0.31,-0.16 0.31,0.16, height 0.26
0201#2 [mm] "Data from Kemet datasheet CC101_COM dated 7/28/11"
  rect 0.46x0.42 smd mask+0.048: 1(-0.33,0) 2(0.33,0)
  body extent -0.31,-0.16 0.31,0.16, height 0.26
0201_033 [mm] "SMD, 2-Leads, Height 0.33mm"
  rect 0.46x0.42 smd mask+0.048: 1(-0.33,0) 2(0.33,0)
  body extent -0.31,-0.16 0.31,0.16, height 0.33
0201L [mm] "Data from Kemet datasheet CC101_COM dated 7/28/11"
  rect 0.36x0.32 smd mask+0.048: 1(-0.28,0) 2(0.28,0)
  body extent -0.31,-0.16 0.31,0.16, height 0.26
0402L [mm] "0402 from SM-752 data"
  rect 0.6x0.5 smd: 1(-0.5,0) 2(0.5,0)
  body extent -0.55,-0.3 0.55,0.3, height 0.6
0402L_cap [mm] "0402 from SM-752 data"
  rect 0.6x0.5 smd: 1(-0.5,0) 2(0.5,0)
  body extent -0.55,-0.3 0.55,0.3, height 0.6
0603L [mm] "0603 from SM-752 data"
  rect 0.8x0.85 smd: 1(-0.7,0) 2(0.7,0)
  silkscreen extent -0.07,-0.33 0.07,0.33, body extent -0.87,-0.47 0.87,0.47, height 1
0603L_cap [mm] "0603 from SM-752 data"
  rect 0.8x0.85 smd: 1(-0.7,0) 2(0.7,0)
  silkscreen extent -0.07,-0.33 0.07,0.33, body extent -0.87,-0.47 0.87,0.47, height 1
0805_HV [mil] "0805 with 30mil clearance between pads"
  rect 50x63 smd: 1(-40,0) 2(40,0)
  silkscreen extent -74,-40 74,40, body extent -43,-29 43,29, height 57
0805L [mm] "0805 from SM-752 data"
  rect 1.1x1.4 smd: 1(-0.75,0) 2(0.75,0)
  body extent -1.1,-0.72 1.1,0.72, height 1.45
1206_190L [mm] "1206_190"
  rect 1.1x1.75 smd: 1(-1.35,0) 2(1.35,0)
  silkscreen extent -0.4,-0.77 0.4,0.77, body extent -1.75,-0.95 1.75,0.95, height 1.9
AssemblyNote [mil] "Assembly Note"
AssemblyNoteLabel [mil] "Assembly Note for PCB Labels"
DBV0005A [mm] "SOT23, 5-Leads, Body 2.9x1.6mm, Pitch 0.95mm, Lead Span 2.8mm, IPC High Density"
  rrect18% 1.1x0.6 smd mask+0.07: 1(-1.3,0.95) 2(-1.3,0) 3(-1.3,-0.95) 4(1.3,-0.95) 5(1.3,0.95)
  silkscreen extent -0.35,-1.55 0.35,1.55, body extent -1.42,-1.46 1.42,1.46, height 1.09
DBV0006A [mm] "SOT23, 6-Leads, Body 2.9x1.6mm, Pitch 0.95mm, Lead Span 2.8mm, IPC High Density"
  rrect18% 1.1x0.6 smd mask+0.07: 1(-1.3,0.95) 2(-1.3,0) 3(-1.3,-0.95) 4(1.3,-0.95) 5(1.3,0) 6(1.3,0.95)
  silkscreen extent -0.35,-1.55 0.35,1.55, body extent -1.5,-1.5 1.5,1.5, height 1.3
DCK0005A [mm] "SOT353, 5-Leads, Body 2x1.3mm, Pitch 0.65mm, Lead Span 2.1mm, IPC High Density"
  rrect25% 0.9x0.4 smd mask+0.05: 1(-1.1,0.65) 2(-1.1,0) 3(-1.1,-0.65) 4(1.1,-0.65) 5(1.1,0.65)
  silkscreen extent -0.25,-1.1 0.25,1.1, body extent -1.14,-1 1.14,1, height 0.95
DQK0006C [mm] "WSON"
  rrect12% 0.9x0.86 on Bottom Paste: 0(0,0.325)
  rrect34% 0.7x0.29 on Bottom Paste: 0(0.095,-0.65)
  rrect33% 0.45x0.3 smd: 1(-0.975,0.65) 2(-0.975,0) 3(-0.975,-0.65) 4(0.975,-0.65) 5(0.975,0) 6(0.975,0.65)
  rrect33% 0.75x0.3 smd paste-0.15: 7(0.095,-0.65)
  rrect11% 1x0.95 smd paste-0.5: 8(0,0.325)
  silkscreen extent -1.15,-1.15 1.15,1.15, body extent -1,-1 1,1, height 0.82
DRB0008A [mm] "VSON-8"
  rrect32% 0.6x0.31 smd mask+0.07: 1(-1.4,0.975) 2(-1.4,0.325) 3(-1.4,-0.325) 4(-1.4,-0.975) 5(1.4,-0.975) 6(1.4,-0.325) 7(1.4,0.325) 8(1.4,0.975)
  round 0.454 hole 0.2 mask+0.05: 9(-0.5,0) 9(0,0.625) 9(0,-0.625) 9(0.5,0)
  round 0.025 smd paste-1.75 mask+0.07: 9(0,0)
  Top Layer region: -0.7,-0.875 -0.49,-0.875 -0.471,-0.879 -0.455,-0.89 -0.444,-0.906 -0.44,-0.925 -0.44,-0.925 -0.44,-1.65 -0.436,-1.669 -0.425,-1.685 -0.409,-1.696 -0.39,-1.7 -0.39,-1.7 -0.26,-1.7 -0.241,-1.696 -0.225,-1.685 -0.214,-1.669 -0.21,-1.65 -0.21,-1.65 -0.21,-0.925 -0.206,-0.906 -0.195,-0.89 -0.179,-0.879 -0.16,-0.875 -0.16,-0.875 0.16,-0.875 0.179,-0.879 0.195,-0.89 0.206,-0.906 0.21,-0.925 0.21,-0.925 0.21,-1.65 0.21,-1.65 0.214,-1.669 0.225,-1.685 0.241,-1.696 0.26,-1.7 0.26,-1.7 0.39,-1.7 0.409,-1.696 0.425,-1.685 0.436,-1.669 0.44,-1.65 0.44,-1.65 0.44,-0.925 0.444,-0.906 0.455,-0.89 0.471,-0.879 0.49,-0.875 0.49,-0.875 0.7,-0.875 0.719,-0.871 0.735,-0.86 0.746,-0.844 0.75,-0.825 0.75,-0.825 0.75,0.825 0.746,0.844 0.735,0.86 0.719,0.871 0.7,0.875 0.7,0.875 0.49,0.875 0.471,0.879 0.455,0.89 0.444,0.906 0.44,0.925 0.44,0.925 0.44,1.65 0.436,1.669 0.425,1.685 0.409,1.696 0.39,1.7 0.39,1.7 0.26,1.7 0.241,1.696 0.225,1.685 0.214,1.669 0.21,1.65 0.21,1.65 0.21,1.65 0.21,0.925 0.206,0.906 0.195,0.89 0.179,0.879 0.16,0.875 0.16,0.875 -0.16,0.875 -0.179,0.879 -0.195,0.89 -0.206,0.906 -0.21,0.925 -0.21,0.925 -0.21,1.65 -0.214,1.669 -0.225,1.685 -0.241,1.696 -0.26,1.7 -0.26,1.7 -0.39,1.7 -0.409,1.696 -0.425,1.685 -0.436,1.669 -0.44,1.65 -0.44,1.65 -0.44,0.925 -0.444,0.906 -0.455,0.89 -0.471,0.879 -0.49,0.875 -0.49,0.875 -0.7,0.875 -0.719,0.871 -0.735,0.86 -0.746,0.844 -0.75,0.825 -0.75,0.825 -0.75,-0.825 -0.746,-0.844 -0.735,-0.86 -0.719,-0.871 -0.7,-0.875
  silkscreen extent -1.73,-1.73 1.73,1.73, body extent -1.5,-1.5 1.5,1.5, height 0.77
DRC0010J [mm] "VSON-10"
  rrect42% 0.6x0.24 smd: 1(-1.4,1) 2(-1.4,0.5) 3(-1.4,0) 4(-1.4,-0.5) 5(-1.4,-1) 6(1.4,-1) 7(1.4,-0.5) 8(1.4,0) 9(1.4,0.5) 10(1.4,1)
  rrect12% 1.65x2.4 smd paste-1 mask-2: 11(0,0)
  Top Layer region: -0.375,-1.65 -0.375,-1.2 -0.775,-1.2 -0.794,-1.196 -0.81,-1.185 -0.821,-1.169 -0.825,-1.15 -0.825,-1.15 -0.825,1.15 -0.821,1.169 -0.81,1.185 -0.794,1.196 -0.775,1.2 -0.775,1.2 -0.375,1.2 -0.375,1.65 -0.371,1.669 -0.36,1.685 -0.344,1.696 -0.325,1.7 -0.325,1.7 -0.325,1.7 -0.175,1.7 -0.175,1.7 -0.156,1.696 -0.14,1.685 -0.129,1.669 -0.125,1.65 -0.125,1.65 -0.125,1.2 0.125,1.2 0.125,1.65 0.129,1.669 0.14,1.685 0.156,1.696 0.175,1.7 0.175,1.7 0.175,1.7 0.325,1.7 0.325,1.7 0.344,1.696 0.36,1.685 0.371,1.669 0.375,1.65 0.375,1.65 0.375,1.2 0.775,1.2 0.794,1.196 0.81,1.185 0.821,1.169 0.825,1.15 0.825,1.15 0.825,-1.15 0.821,-1.169 0.81,-1.185 0.794,-1.196 0.775,-1.2 0.775,-1.2 0.375,-1.2 0.375,-1.65 0.371,-1.669 0.36,-1.685 0.344,-1.696 0.325,-1.7 0.325,-1.7 0.175,-1.7 0.156,-1.696 0.14,-1.685 0.129,-1.669 0.125,-1.65 0.125,-1.65 0.125,-1.2 -0.125,-1.2 -0.125,-1.65 -0.129,-1.669 -0.14,-1.685 -0.156,-1.696 -0.175,-1.7 -0.175,-1.7 -0.325,-1.7 -0.344,-1.696 -0.36,-1.685 -0.371,-1.669 -0.375,-1.65
  body extent -1.5,-1.5 1.5,1.5, height 1
FCC_disclaimer [mil]
Fiducial10-20 [mm]
  round 1 smd mask+0.203: 1(0,0)
FP-1101M2S3CGE2_SIP3-MFG [mm]
  rrect4% 2.8x2.8 hole 1.85 paste-1000 mask+0: 1(0,4.7)
  round 2.8 hole 1.85 paste-1000 mask+0: 2(0,0) 3(0,-4.7)
  silkscreen extent -3.3,-6.35 3.3,6.35, body extent -3.4,-6.45 3.4,6.45, height 0.25
FP-2116-440-AL_STANDOFF_HEX_1-4-MFG [mm]
  round 3.2 hole 3.2 unplated paste-1000 mask+0: ""(0,0)
  body extent -3.66,-3.17 3.66,3.18, height 31.88
FP-132134-15_CONN_SMA_JACK-MFG [mm]
  round 1.5 smd paste+0 mask+0: 1(0,0)
  round 2.6 hole 1.7 paste-1000 mask+0: 2(-2.54,2.54) 3(2.54,2.54) 4(-2.54,-2.54) 5(2.54,-2.54)
  silkscreen extent -0.86,-3.6 0.86,-3.6, body extent -3.94,-3.94 3.94,3.94, height 0.25
FP-ADT2-1T+_SMD6-MFG [mil]
  rrect6% 100x65 smd paste+0 mask+0: 1(-100,100) 2(-100,0) 3(-100,-100) 4(100,-100) 5(100,0) 6(100,100)
  silkscreen extent -183,-158 112,158, body extent -154,-161 154,161, height 10
FP-SF-1206FP100-2_1206-MFG [mm]
  rrect8% 1.25x1.65 smd paste+0 mask+0: 1(-1.725,0) 2(1.725,0)
  silkscreen extent -0.72,-0.82 0.72,0.82, body extent -1.55,-0.77 1.55,0.77, height 0.7
FSMSM [mm]
  rrect10% 2.2x1.6 smd: 1(-4.6,0) 2(4.6,0)
  body extent -4.98,-1.75 4.98,1.75, height 4.4
FTDI_Dongle_003 [mm]
  rect 2.27x0.279 smd: 1(18.74,-7.25) 2(13.01,-7.25) 3(18.74,-6.75) 4(13.01,-6.75) 5(18.74,-6.25) 6(13.01,-6.25) 7(18.74,-5.75) 8(13.01,-5.75) 9(18.74,-5.25) 10(13.01,-5.25) 11(18.74,-4.75) 12(13.01,-4.75) 13(18.74,-4.25) 14(13.01,-4.25) 15(18.74,-3.75) 16(13.01,-3.75) 17(18.74,-3.25) 18(13.01,-3.25) 19(18.74,-2.75) 20(13.01,-2.75) 21(18.74,-2.25) 22(13.01,-2.25) 23(18.74,-1.75) 24(13.01,-1.75) 25(18.74,-1.25) 26(13.01,-1.25) 27(18.74,-0.75) 28(13.01,-0.75) 29(18.74,-0.25) 30(13.01,-0.25) 31(18.74,0.25) 32(13.01,0.25) 33(18.74,0.75) 34(13.01,0.75) 35(18.74,1.25) 36(13.01,1.25) 37(18.74,1.75) 38(13.01,1.75) 39(18.74,2.25) 40(13.01,2.25) 41(18.74,2.75) 42(13.01,2.75) 43(18.74,3.25) 44(13.01,3.25) 45(18.74,3.75) 46(13.01,3.75) 47(18.74,4.25) 48(13.01,4.25) 49(18.74,4.75) 50(13.01,4.75) 51(18.74,5.25) 52(13.01,5.25) 53(18.74,5.75) 54(13.01,5.75) 55(18.74,6.25) 56(13.01,6.25) 57(18.74,6.75) 58(13.01,6.75) 59(18.74,7.25) 60(13.01,7.25)
  round 2 hole 2.45 unplated: 4(-19.685,-10.16) 4(-19.685,10.16)
  round 0 hole 1.02 unplated: MH1(13.205,-10.065) MH2(13.205,10.065)
  rect 0.43x2.54 smd: MP1(15.875,-8.065) MP4(15.875,8.065)
  rect 0.43x4.7 smd: MP2(15.875,-3.175) MP3(15.875,3.175)
  silkscreen extent 12.26,-10.66 19.78,10.65, body extent -22.22,-12.7 22.22,13.2, height 10.54
HNSS256 [mil] "Hex Nut 2-56"
  body extent -94,-108 94,108, height 31
Keystone5000 [mil] "For Keystone 500x miniature loop terminals"
  round 80 hole 40: 1(0,0)
  silkscreen extent -52,-52 52,52, body extent -49,-49 49,49, height 182
Keystone5010 [mil] "Keystone Multipurpose loops"
  round 87 hole 63: 1(0,0)
  silkscreen extent -70,-70 70,70, body extent -63,-63 63,62, height 319
Keystone5011 [mil] "Keystone Multipurpose loops"
  round 87 hole 63: 1(0,0)
  silkscreen extent -70,-70 70,70, body extent -63,-63 63,62, height 319
Keystone5013 [mil] "Keystone Multipurpose loops"
  round 87 hole 63: 1(0,0)
  silkscreen extent -70,-70 70,70, body extent -63,-63 63,62, height 319
Keystone5129 [mil] "Keystone Multipurpose loops"
  round 87 hole 63: 1(0,0)
  silkscreen extent -70,-70 70,70, body extent -63,-63 63,62, height 319
Label_650x200 [mil] "Thermal Transfer Label"
  round 1 on Mech13: 0(0,0)
  silkscreen extent -325,-100 325,100, body extent -325,-100 325,100, height 1
LED_LTST-C190-Green [mm] "Lite-On"
  rect 0.8x0.8 smd: 1(-0.75,0) 2(0.75,0)
  silkscreen extent -1.1,-0.8 1.8,0.8, body extent -0.85,-0.45 0.85,0.45, height 0.91
NFM31PC [mm]
  rrect10% 0.95x1.2 smd paste+0: 1(-1.675,0) 3(1.675,0)
  round 0.2 / inner round 0.454 / far side round 0.454 hole 0.2 mask+0.05: 2(-0.305,-1.105) 2(-0.305,1.105) 2(0.305,-1.105) 2(0.305,1.105)
  rrect10% 1x1 smd paste+0: 2(0,-0.8) 2(0,0.8)
  body extent -1.7,-0.9 1.7,0.9, height 1.5
PBC02SAAN [mm] "Sullins 100mil, 1x2, 230 mil above insulator"
  rect 1.65x1.65 hole 1.016: 1(0,1.27)
  round 1.65 hole 1.016: 2(0,-1.27)
  silkscreen extent -1.27,-2.54 1.6,2.54, body extent -1.27,-2.54 1.27,2.54, height 8.38
PBC04DAAN [mm]
  rect 1.65x1.65 hole 1.016: 1(-1.27,3.81)
  round 1.65 hole 1.016: 2(1.27,3.81) 3(-1.27,1.27) 4(1.27,1.27) 5(-1.27,-1.27) 6(1.27,-1.27) 7(-1.27,-3.81) 8(1.27,-3.81)
  silkscreen extent -2.54,-5.08 2.54,5.49, body extent -2.54,-5.08 2.54,5.08, height 8.14
ProbePoint_TH_40mil [mil]
  round 41 hole 28: 1(0,0)
RAPC722X [mm] "Conn_DC Jack"
  oval 1.7x4.3 hole 1.01 slot 3.56 at 90 deg: 1(14.194,0)
  oval 1.5x3.8 hole 0.76 slot 3.05 at 90 deg: 2(7.946,0)
  oval 3.8x1.5 hole 0.76 slot 3.05 at 0 deg: 3(11.197,-4.7)
  silkscreen extent 0.2,-4.57 14.93,4.57, body extent 0.58,-4.97 15.06,4.56, height 10.92
RGT0016A_NV [mm] "QFN, 16-Leads, Body 3x3mm, Pitch 0.5mm, Thermal Pad 1.45x1.45mm, TI Recommended"
  rrect42% 0.6x0.24 smd: 1(-1.4,0.75) 2(-1.4,0.25) 3(-1.4,-0.25) 4(-1.4,-0.75) 9(1.4,-0.75) 10(1.4,-0.25) 11(1.4,0.25) 12(1.4,0.75)
  rrect42% 0.24x0.6 smd: 5(-0.75,-1.4) 6(-0.25,-1.4) 7(0.25,-1.4) 8(0.75,-1.4) 13(0.75,1.4) 14(0.25,1.4) 15(-0.25,1.4) 16(-0.75,1.4)
  rrect7% 1.34x1.34 on Bottom Paste: 17(0,0)
  rrect7% 1.45x1.45 smd paste-0.725: 17(0,0)
  silkscreen extent -1.72,-1.73 1.72,1.73, body extent -1.57,-1.57 1.58,1.58, height 1.01
RPU0010A [mm] "VQFN-10"
  rrect50% 0.65x0.2 smd: 1(-0.875,0.25) 3(-0.875,-0.75) 5(0.875,-0.25)
  rrect50% 1x0.2 smd: 2(-0.7,-0.25) 4(0.7,-0.75) 6(0.7,0.25)
  rrect50% 0.25x0.55 smd: 7(0.75,0.925) 8(0.25,0.925) 9(-0.25,0.925) 10(-0.75,0.925)
  silkscreen extent -1.2,0.6 -1.1,0.8, body extent -1.05,-1.05 1.05,1.05, height 1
